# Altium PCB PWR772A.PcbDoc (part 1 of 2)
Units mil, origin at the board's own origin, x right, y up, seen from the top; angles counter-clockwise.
Board outline 3500 x 3300 mil, 4 copper layers (Top Layer, Signal Layer 1, Signal Layer 2, Bottom Layer), stack 30.2 mil thick; 164 components, 50 nets, 349 pads, 587 vias.
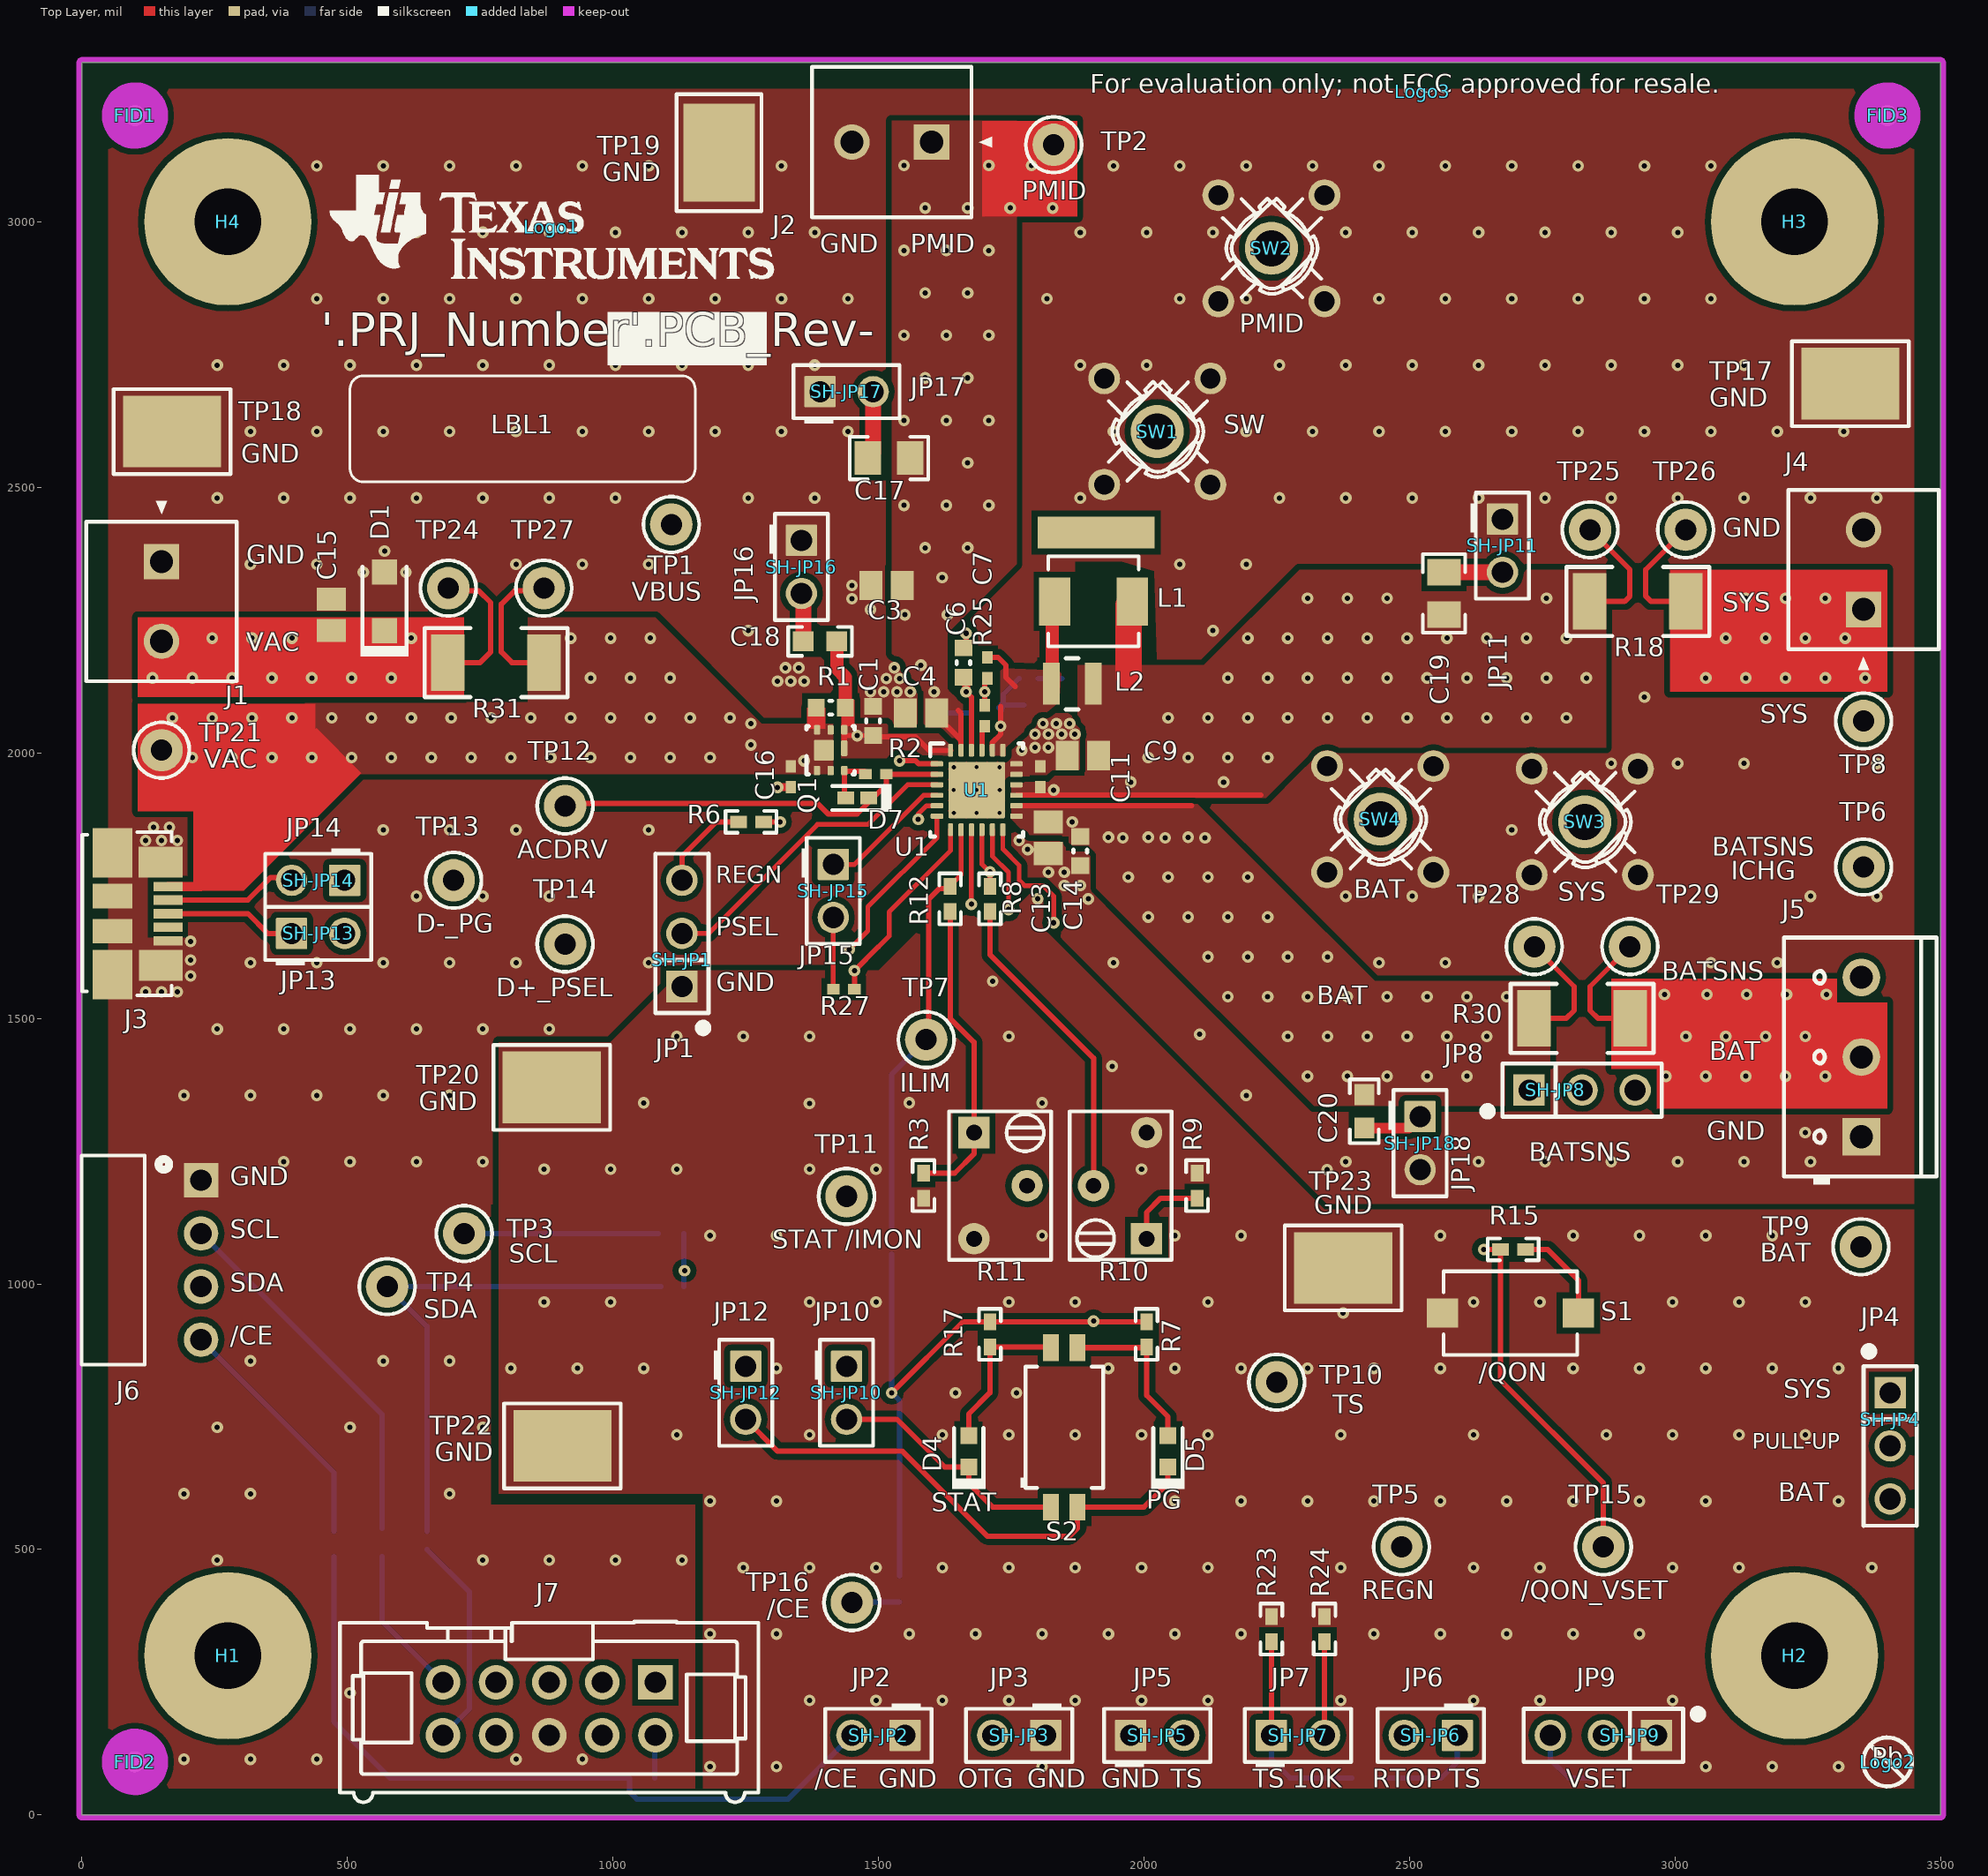
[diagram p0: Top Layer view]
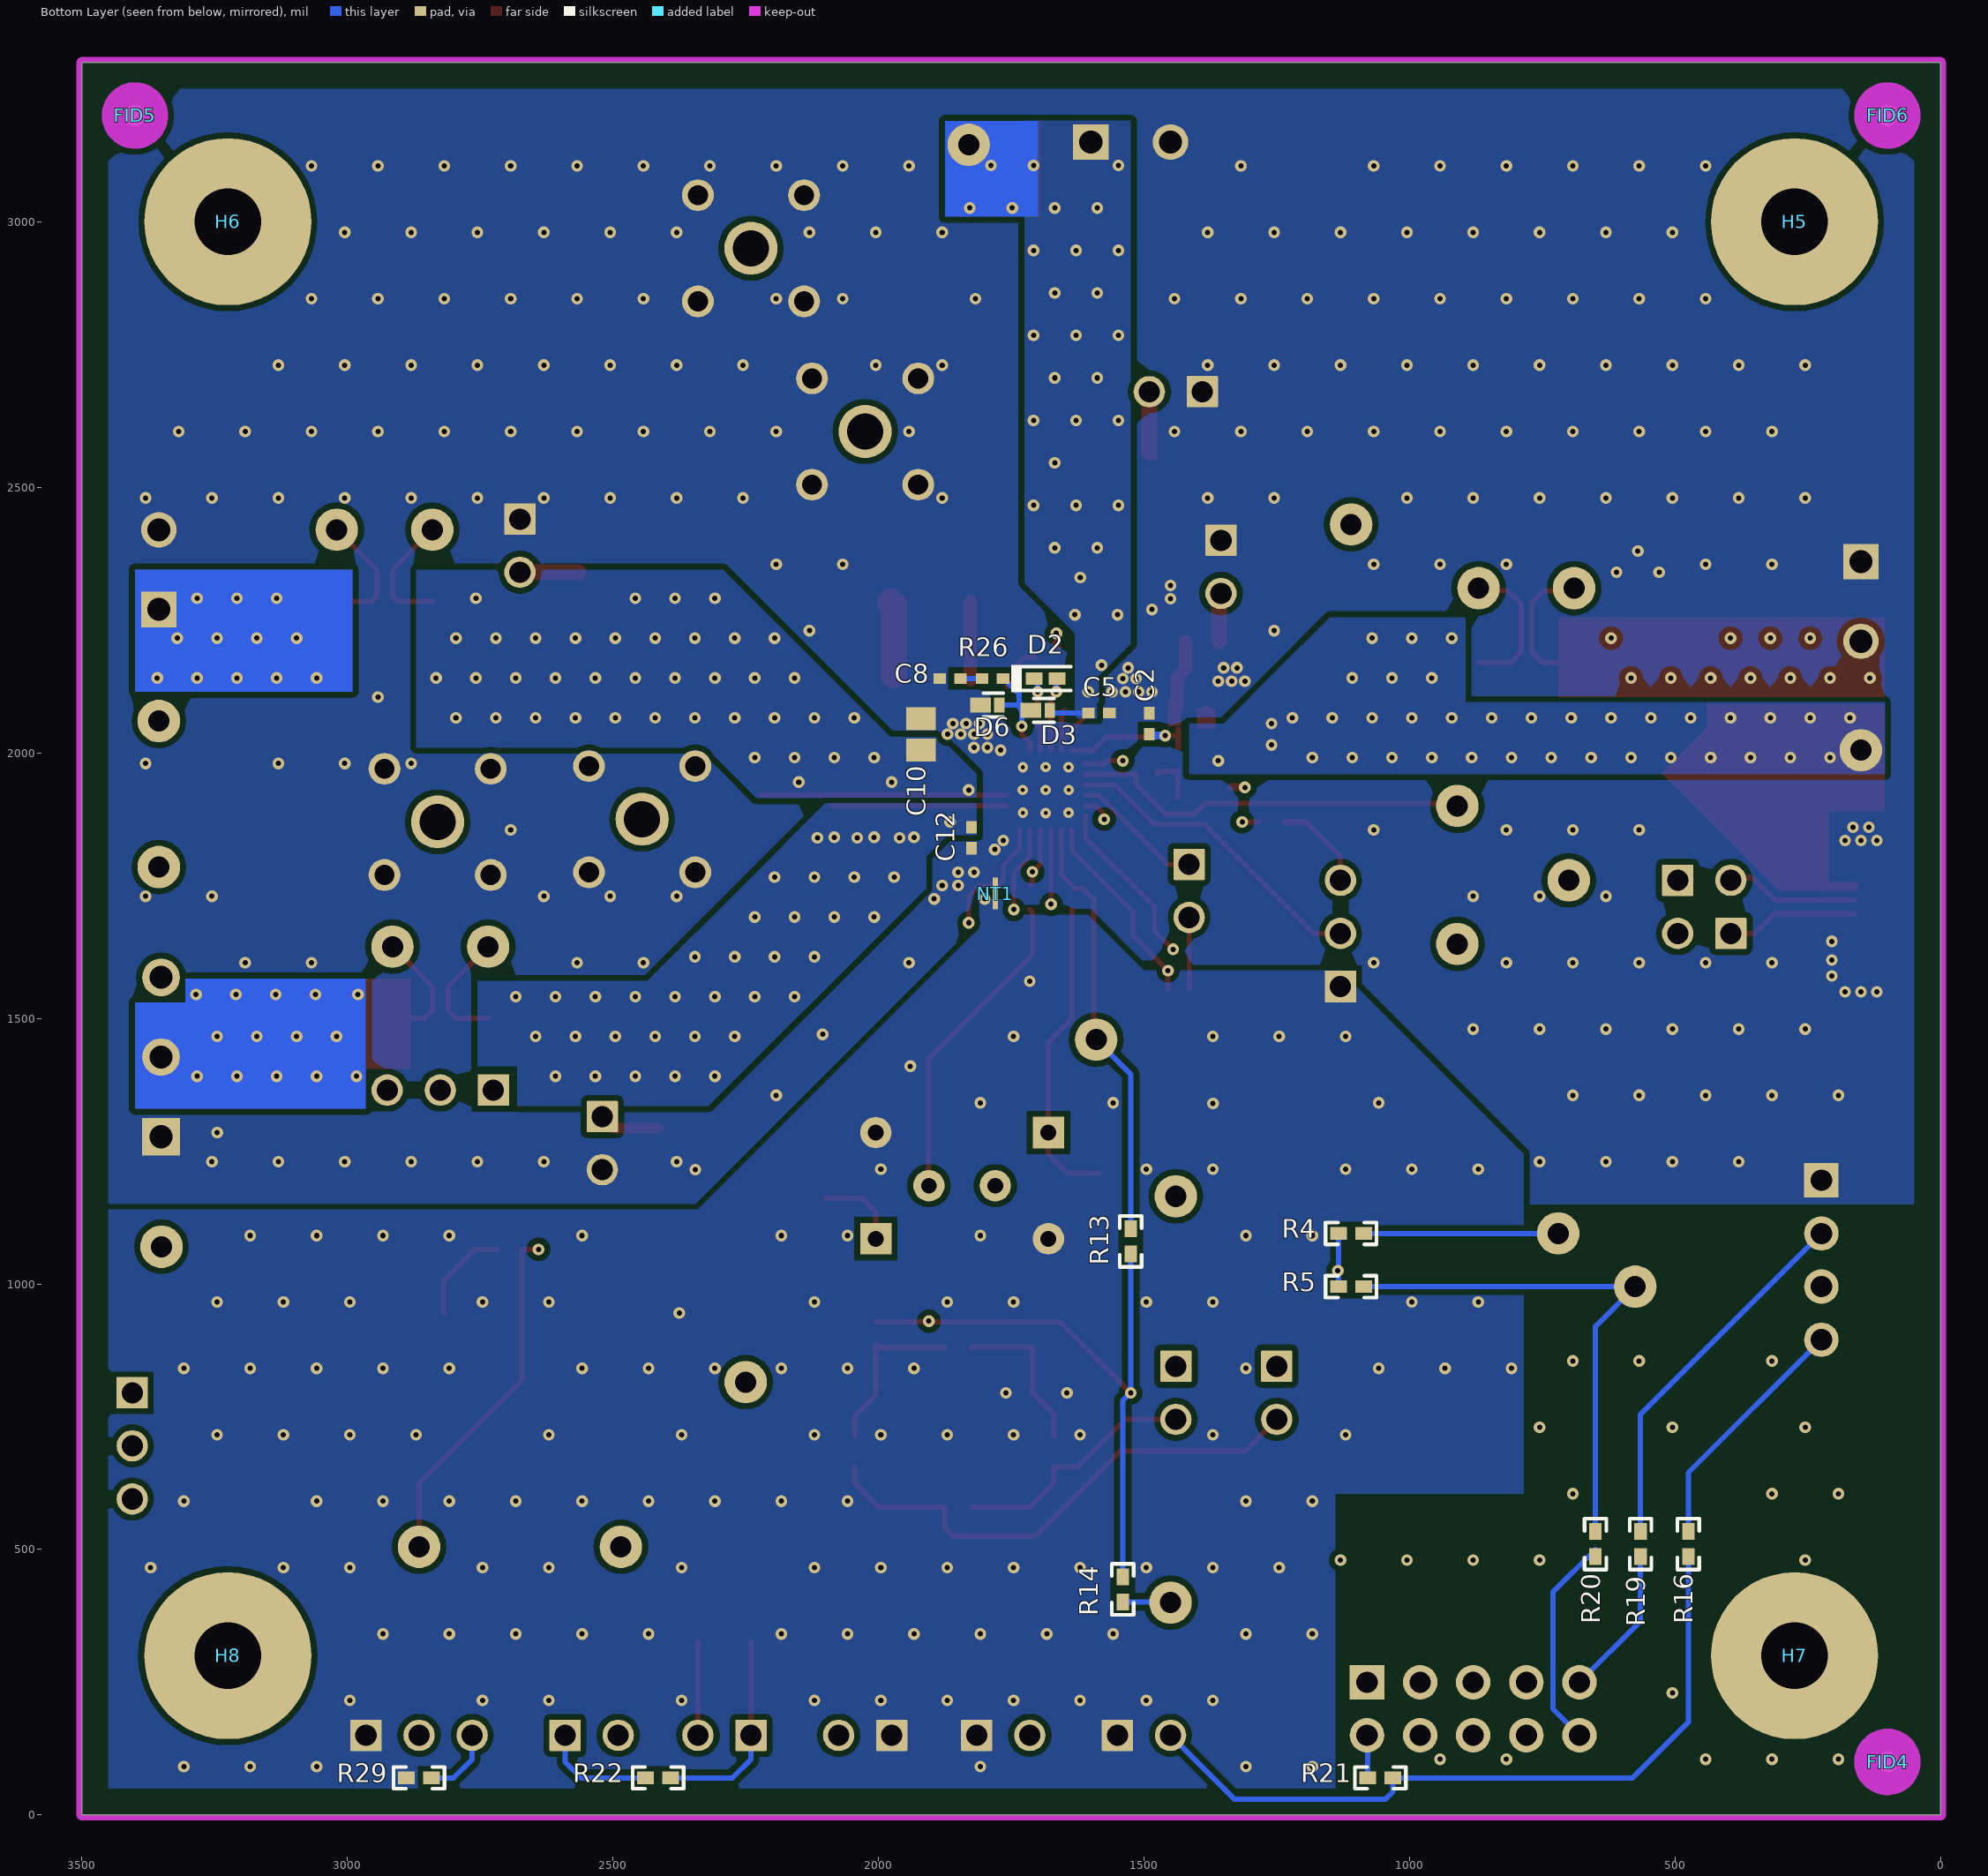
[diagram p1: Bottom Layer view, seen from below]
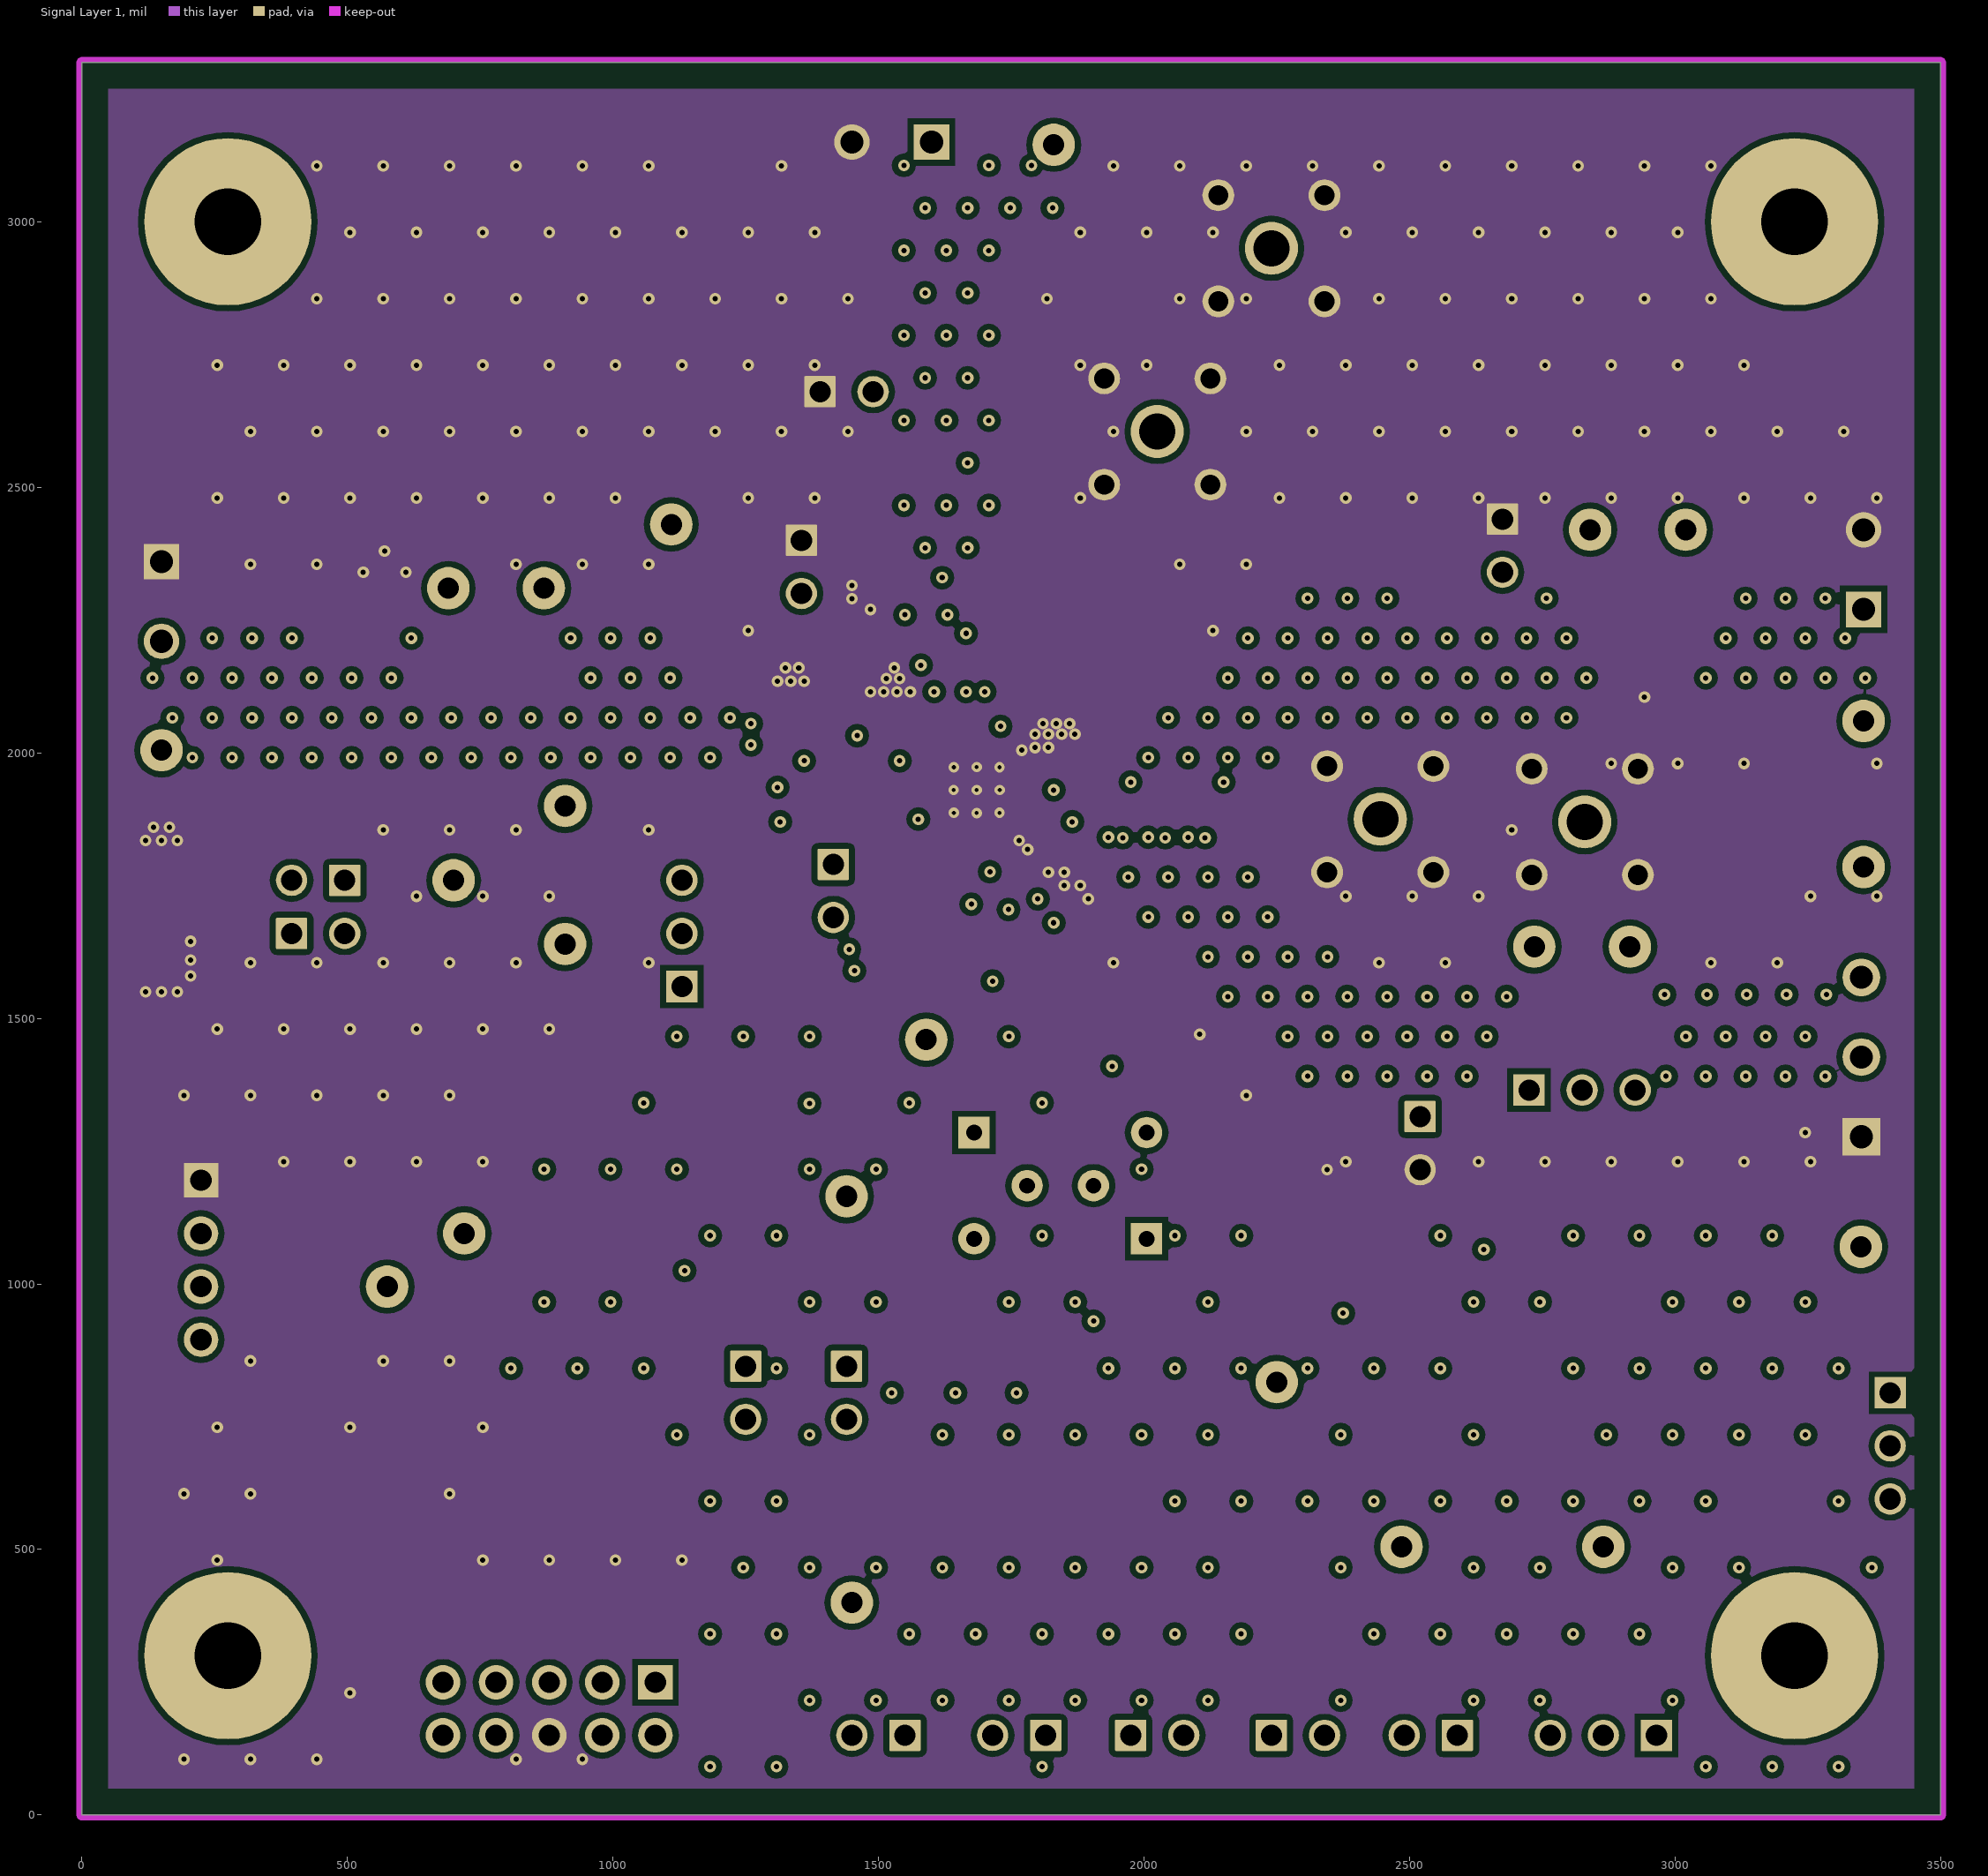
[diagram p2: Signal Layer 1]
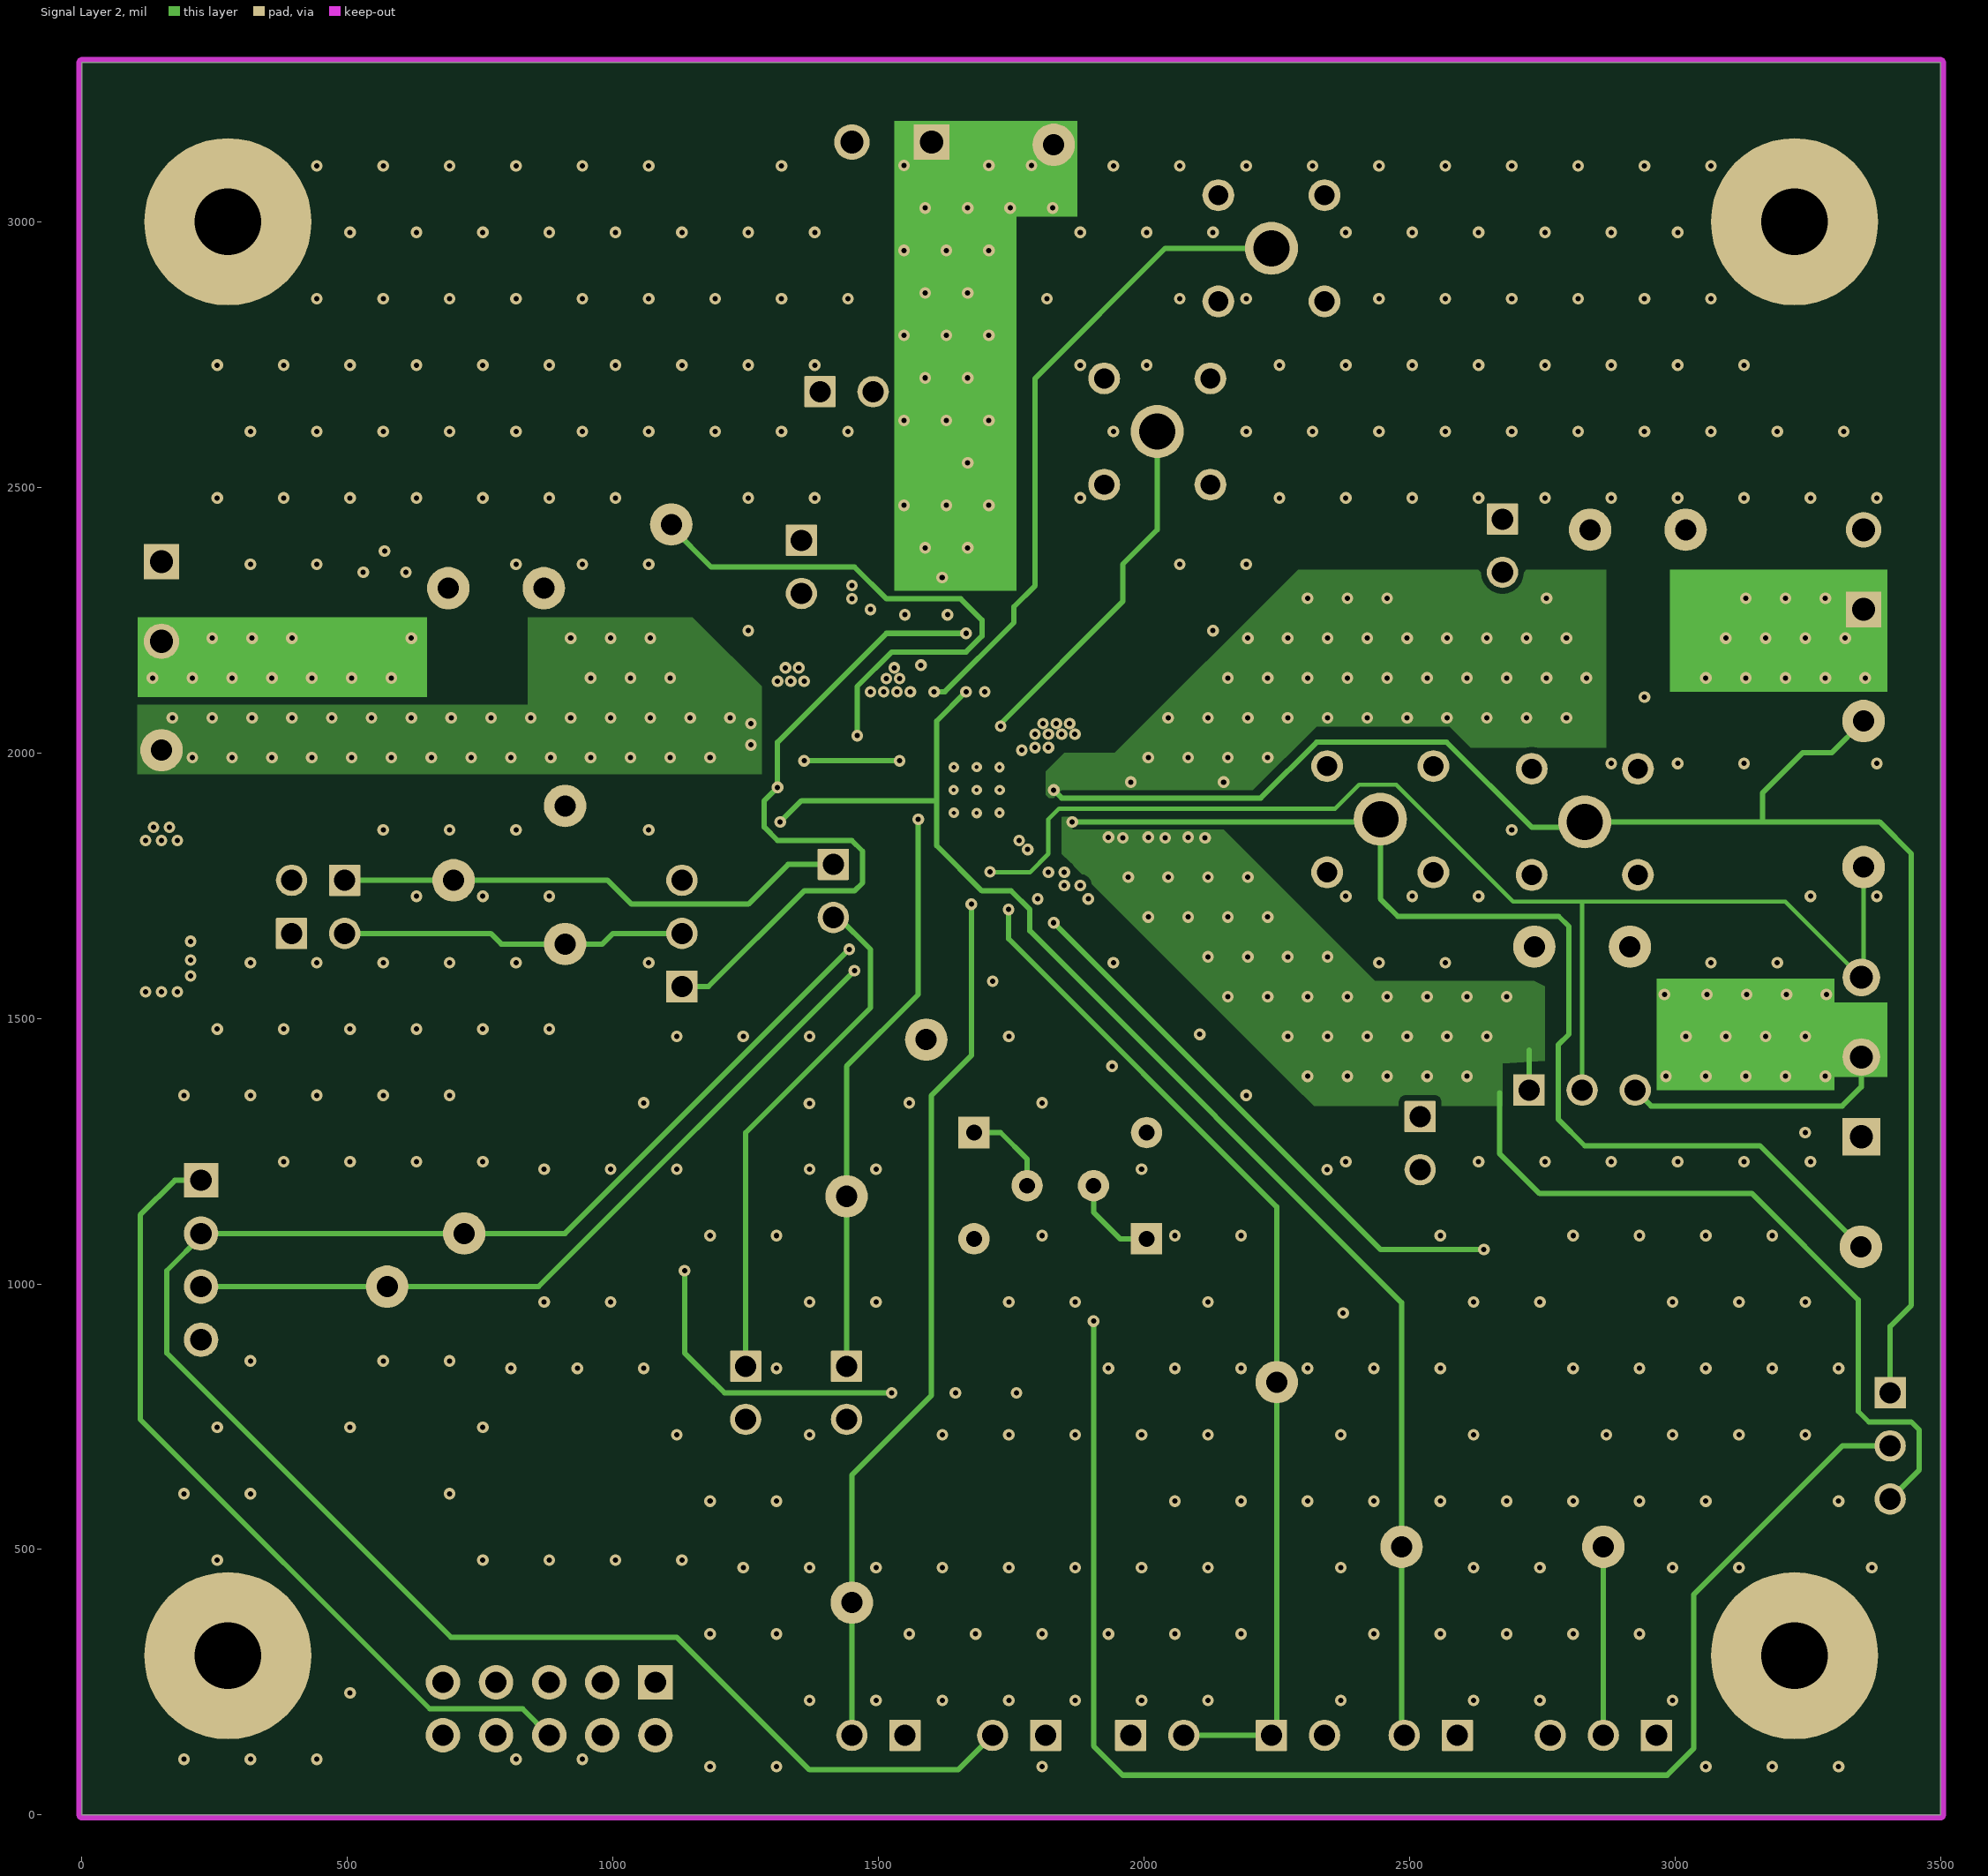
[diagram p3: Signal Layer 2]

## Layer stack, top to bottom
Top Solder: solder mask 0.4, Solder Resist, Dk 3.5
Top Layer: signal copper 1.4
Dielectric1: core 8.2, FR-4 High TG, Dk 4.8
Signal Layer 1: signal copper 1.4
Dielectric 2: core 8.2, FR-4 High TG, Dk 4.8
Signal Layer 2: signal copper 1.4
Dielectric 3: core 8.2, FR-4 High TG, Dk 4.8
Bottom Layer: signal copper 1.4
Bottom Solder: solder mask 0.4, Solder Resist, Dk 3.5

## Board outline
0,0 0,3300 3500,3300 3500,0

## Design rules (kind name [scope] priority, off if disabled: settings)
AcuteAngle [All] p1: minimum=4.50000000000000E+0001 checktracksonly=FALSE
AssemblyTestPointUsage [All] p1: valid=2
BoardOutlineClearance BoardOutlineClearance_MountingHoles [OnCopper and InComponentClass('Mounting Holes')] p1: gap=40
BoardOutlineClearance BoardOutlineClearance_Poly [OnCopper and InPoly] p2: gap=25
BoardOutlineClearance [OnCopper and Not InComponentClass('Logo') and not InComponentClass('FiducialMark') and not InRegion(1000,500,4000,800)] p3: gap=20
Clearance Clearance_D3-D6 [InComponent('D3')  or InComponent('D6')] p1: gap=7.8 except(5.1: SMDPad-SMDPad)
Clearance Clearance_Poly [InPolygon] p2: gap=11
Clearance [All] p3: gap=7.87
ComponentClearance ComponentClearance_JP13,14 [InComponent('JP13')  or InComponent('SH-JP13') vs InComponent('JP14')   or InComponent('SH-JP14')] p1: gap=0 collisioncheckmode=3 verticalgap=0 showdistances=FALSE
ComponentClearance ComponentClearance_MountingHoles_FiducialMarks [InComponentClass('Mounting Holes') vs InComponentClass('FiducialMark')] p2: gap=40 collisioncheckmode=3 verticalgap=10 showdistances=FALSE
ComponentClearance ComponentClearance_Shunt [InComponentClass('Header') vs InComponentClass('Shunt')] p3: gap=0 collisioncheckmode=3 verticalgap=0 showdistances=FALSE
ComponentClearance ComponentClearance_Logo [InComponentClass('Logo')] p4: gap=0 collisioncheckmode=3 verticalgap=0 showdistances=FALSE
ComponentClearance ComponentClearance_ScrewToNut [(HasFootprint('NY PMS 440 0025 PH')) vs (HasFootprint('Keystone_1902C'))] p5: gap=5 collisioncheckmode=3 verticalgap=10 showdistances=FALSE
ComponentClearance ComponentClearance_MountingHoles [InComponentClass('Mounting Holes')] p6: gap=40 collisioncheckmode=3 verticalgap=0 showdistances=FALSE
ComponentClearance ComponentClearance_SmallPassives [HasFootprint('0201*') or HasFootprint('0402*') or HasFootprint('0508') or HasFootprint('0603*') or HasFootprint('0612') or HasFootprint('0805*') or HasFootprint('0815*') or HasFootprint('0830*') or HasFootprint('1206*') or HasFootprint('1210*') or HasFootprint('1808*') or HasFootprint('1812*') or HasFootprint('1825*') or HasFootprint('2010*') or HasFootprint('2220*') or HasFootprint('2225*') or HasFootprint('2512*') or HasFootprint('2728*') or HasFootprint('3518*') vs HasFootprint('0201*') or HasFootprint('0402*') or HasFootprint('0508') or HasFootprint('0603*') or HasFootprint('0612') or HasFootprint('0805*') or HasFootprint('0815*') or HasFootprint('0830*') or HasFootprint('1206*') or HasFootprint('1210*') or HasFootprint('1808*') or HasFootprint('1812*') or HasFootprint('1825*') or HasFootprint('2010*') or HasFootprint('2220*') or HasFootprint('2225*') or HasFootprint('2512*') or HasFootprint('2728*') or HasFootprint('3518*')] p7: gap=10 collisioncheckmode=3 verticalgap=10 showdistances=FALSE
ComponentClearance ComponentClearance_THtoSMT [IsThruComponent vs IsSMTComponent] p8: gap=20 collisioncheckmode=3 verticalgap=20 showdistances=FALSE
ComponentClearance ComponentClearance_THtoTH [IsThruComponent vs IsThruComponent] p9: gap=30 collisioncheckmode=3 verticalgap=30 showdistances=FALSE
ComponentClearance [All] p10: gap=15 collisioncheckmode=3 verticalgap=10 showdistances=FALSE
DiffPairsRouting [All] p1: maxlimit=100 minlimit=10 mostfreqgap=10 toplayer_minwidth=15 toplayer_maxwidth=15 toplayer_prefwidth=15 midlayer1_minwidth=15 midlayer1_maxwidth=15 midlayer1_prefwidth=15 midlayer2_minwidth=15 midlayer2_maxwidth=15 midlayer2_prefwidth=15 bottomlayer_minwidth=15 bottomlayer_maxwidth=15 bottomlayer_prefwidth=15 maxuncoupledlength=1000
FabricationTestPointUsage TestPointUsage [All] p1: valid=2 allowmultiple=FALSE
FabricationTestpoint Testpoint [All] p1: side=3 testpointundercomponent=TRUE minsize=40 maxsize=100 preferedsize=60 minholesize=0 maxholesize=40 preferedholesize=32 testpointgrid=1 allowsidetop=TRUE allowsidebottom=TRUE usegrid=TRUE gridtolerance=0.01
FanoutControl Fanout_LCC [IsLCC] p1: bgadir=Out bgaviamode=Centered fanoutstyle=Auto fanoutdirection=Alternating viagrid=1 // Fanout_LCC (Default Rule)
FanoutControl Fanout_BGA [IsBGA] p2: bgadir=Out bgaviamode=Centered fanoutstyle=Auto fanoutdirection=Alternating viagrid=1 // Fanout_BGA (Default Rule)
FanoutControl Fanout_Default [All] p4: bgadir=Out bgaviamode=Centered fanoutstyle=Auto fanoutdirection=Alternating viagrid=1 // Fanout_Default (Default Rule)
FanoutControl Fanout_Small [(CompPinCount < 5)] p5: bgadir=Out bgaviamode=Centered fanoutstyle=Auto fanoutdirection=OutThenIn viagrid=1 // Fanout_Small (Default Rule)
HoleSize [All] p1: absolutevalues=TRUE maxlimit=251 minlimit=7.87 maxpercent=80.000 minpercent=20.000
HoleToHoleClearance HoleToHoleClearance_U1 [InComponent('U1') vs InComponent('U1')] p1: gap=0 allowstackedmicrovias=TRUE
HoleToHoleClearance [All] p2: gap=10 allowstackedmicrovias=TRUE
MinimumAnnularRing MinimumAnnularRing_ThermalPadVias [IsVia and InAnyComponent] p1: minimumring=5.91
MinimumAnnularRing [All] p2: minimumring=5.9
MinimumSolderMaskSliver MinimumSolderMaskSliver_Logo [InComponentClass('Logo') vs InComponentClass('Logo')] p1: minsoldermaskwidth=0.7
MinimumSolderMaskSliver [All] p2: minsoldermaskwidth=3.94
PlaneConnect [All] p1: planeconnectstyle=Relief reliefexpansion=10 reliefentries=4 reliefconductorwidth=10 reliefairgap=10
PolygonConnect [All] p1: connectstyle=Direct reliefconductorwidth=10 reliefentries=4 polygonreliefangle="90 Angle" airgapwidth=10
RoutingVias ThermalPadVias [IsVia and InAnyComponent] p1: holewidth=7.87 width=19.68 viastyle="Through Hole" minholewidth=7.87 minwidth=19.68 maxholewidth=12.99 maxwidth=23.62
RoutingVias [All] p2: holewidth=10 width=26 viastyle="Through Hole" minholewidth=7.87 minwidth=19 maxholewidth=40 maxwidth=65
SilkToBoardRegionClearance [Not ((IsComment or IsDesignator) And (Hide <> 'False')) and not InRegion(1000,500,4000,800)] p1:
SilkToSilkClearance SilkToSilkClearance_Pb-FreeLogo [(HasFootprint('Pb-Free_Overlay_Medium') OR HasFootprint('Pb-Free_Overlay_Small')) vs (HasFootprint('Pb-Free_Overlay_Medium') OR HasFootprint('Pb-Free_Overlay_Small'))] p1: silktosilkclearance=0
SilkToSilkClearance [All] p2: silktosilkclearance=3
SilkToSolderMaskClearance [Istrack and HasFootprint('152AD') vs isfill] p1: minsilkscreentomaskgap=1.7 clearancetoexposedcopper=FALSE
SilkToSolderMaskClearance SilkToComponentPadClearance [IsPad and InAnycomponent] p2: minsilkscreentomaskgap=3 clearancetoexposedcopper=TRUE
SilkToSolderMaskClearance "Silk to Solder Mask Opening" [All] p3: minsilkscreentomaskgap=3 clearancetoexposedcopper=FALSE
SolderMaskExpansion [All] p1: expansion=1.97
Width [All] p1: maxlimit=100 minlimit=7.8 preferedwidth=10 checkconnectedcopper=TRUE
14 further rules are at their usual default settings.

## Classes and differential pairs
component class PWR772A: C1 C2 C3 C4 C5 C6 C7 C8 C9 C10 C11 C12 C13 C14 C15 C16 C17 C18 C19 C20 D1 D2 D3 D4 D5 D6 D7 J1 J2 J3 J4 J5 J6 J7 JP1 JP2 JP3 JP4 JP5 JP6 JP7 JP8 JP9 JP10 JP11 JP12 JP13 JP14 JP15 JP16 JP17 JP18 L1 L2 NT1 Q1 R1 R2 R3 R4 R5 R6 R7 R8 R9 R10 R11 R12 R13 R14 R15 R16 R17 R18 R19 R20 R21 R22 R23 R24 R25 R26 R27 R29 R30 R31 S1 S2 SW1 SW2 SW3 SW4 TP1 TP2 TP3 TP4 TP5 TP6 TP7 TP8 TP9 TP10 TP11 TP12 TP13 TP14 TP15 TP16 TP17 TP18 TP19 TP20 TP21 TP22 TP23 TP24 TP25 TP26 TP27 TP28 TP29 U1
component class Header: JP1 JP2 JP3 JP4 JP5 JP6 JP7 JP8 JP9 JP10 JP11 JP12 JP13 JP14 JP15 JP16 JP17 JP18
component class Logo: Logo1
component class PWR772A_Hdwr: FID1 FID2 FID3 FID4 FID5 FID6 H1 H2 H3 H4 H5 H6 H7 H8 LBL1 Logo1 Logo2 Logo3 SH-JP1 SH-JP2 SH-JP3 SH-JP4 SH-JP5 SH-JP6 SH-JP7 SH-JP8 SH-JP9 SH-JP10 SH-JP11 SH-JP12 SH-JP13 SH-JP14 SH-JP15 SH-JP16 SH-JP17 SH-JP18 ZZ1 ZZ2 ZZ3 ZZ4 ZZ5
component class FiducialMark: FID1 FID2 FID3 FID4 FID5 FID6
component class AssemblyNote: ZZ1 ZZ2 ZZ3 ZZ4 ZZ5
component class Label: LBL1
component class "Mounting Holes": H1 H2 H3 H4
component class Shunt: SH-JP1 SH-JP2 SH-JP3 SH-JP4 SH-JP5 SH-JP6 SH-JP7 SH-JP8 SH-JP9 SH-JP10 SH-JP11 SH-JP12 SH-JP13 SH-JP14 SH-JP15 SH-JP16 SH-JP17 SH-JP18

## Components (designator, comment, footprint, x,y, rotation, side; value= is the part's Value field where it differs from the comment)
C1 "GMK107BJ105KA-T" 0603L 1490,2060 r90 top
C2 "GRM1555C1H102JA01D" 0402L 1490,2055 r90 bottom
C3 "GRM21BR61E106KA73L" 0805L 1515,2315 r180 top
C4 "GRM21BC71E106KE11L" 0805L 1580,2075 r180 top
C5 "GRM1555C1H102JA01D" 0402L 1585,2075 r180 bottom
C6 "GRM188R61C475KAAJ" 0603L 1660,2170 r90 top
C7 "GRM155R71E473KA88D" 0402L 1705,2160 r270 top
C8 "GRM1555C1E111JA01D" 0402L 1865,2140 r0 bottom
C9 "GRM21BR71A106KE51L" 0805L 1885,1995 r180 top
C10 "GRM21BR71A106KE51L" 0805L 1920,2035 r90 bottom
C11 "C1005X7R1E104M050BB" 0402L 1805,1955 r90 top
C12 "GRM1555C1H102JA01D" 0402L 1825,1840 r90 bottom
C13 "GRM21BR71A106KE51L" 0805L 1820,1840 r90 top
C14 "GRM188R61C475KAAJ" 0603L 1880,1815 r90 top
C15 "GRM219R71E105KA88D" 0805L 470,2260 r90 top
C16 "GRM155R71E104KE14D" 0402L 1335,1955 r270 top
C17 "GRM21BR61E106KA73L" 0805_HV 1520,2555 r180 top
C18 "GMK107BJ105KA-T" 0603 1390,2210 r180 top
C19 "GRM21BR71A106KE51L" 0805_HV 2565,2300 r90 top
C20 "GRM188R61C475KAAJ" 0603 2415,1325 r90 top
D1 "PTVS13VS1UR,115" SOD-123W 570,2285 r90 top
D2 "ZLLS350TA" SOD-523 1685,2140 r180 bottom
D3 "NSR10F20NXT5G" 152AD 1700,2080 r0 bottom
D4 "LTST-C190GKT" LED_LTST-C190 1670,685 r270 top
D5 "LTST-C190GKT" LED_LTST-C190 2045,685 r270 top
D6 "NSR10F20NXT5G" 152AD 1795,2090 r0 bottom
D7 "ZLLS350TA" SOD-523 1460,1915 r180 top
FID1 "Fiducial" Fiducial10-30 100,3200 r0 top
FID2 "Fiducial" Fiducial10-30 100,100 r0 top
FID3 "Fiducial" Fiducial10-30 3400,3200 r0 top
FID4 "Fiducial" Fiducial10-30 100,100 r90 bottom
FID5 "Fiducial" Fiducial10-30 3400,3200 r90 bottom
FID6 "Fiducial" Fiducial10-30 100,3200 r90 bottom
H1 "NY PMS 440 0025 PH" "NY PMS 440 0025 PH" 275,300 r0 top
H2 "NY PMS 440 0025 PH" "NY PMS 440 0025 PH" 3225,300 r0 top
H3 "NY PMS 440 0025 PH" "NY PMS 440 0025 PH" 3225,3000 r0 top
H4 "NY PMS 440 0025 PH" "NY PMS 440 0025 PH" 275,3000 r0 top
H5 "1902C" Keystone_1902C 275,3000 r180 bottom
H6 "1902C" Keystone_1902C 3225,3000 r180 bottom
H7 "1902C" Keystone_1902C 275,300 r180 bottom
H8 "1902C" Keystone_1902C 3225,300 r180 bottom
J1 "1727010" PhoenixConact_1727010 150,2285 r270 top
J2 "1727010" PhoenixConact_1727010 1525,3150 r180 top
J3 "0473460001" CONN_47346-0001 0.75,1697.13 r90 top
J4 "1727010" PhoenixConact_1727010 3355,2345 r90 top
J5 "1727023" Phoenix_1727023 3350.75,1427.13 r90 top
J6 "22-05-3041" CONN_22-05-3041 0,1045 r270 top
J7 "N2510-6002-RB" CONN_2510-6002 880,200 r180 top
JP1 "PEC03SAAN" CONN_PEC03SAAN 1130,1660 r90 top
JP2 "PEC02SAAN" CONN_PEC02SAAN 1500,150 r180 top
JP3 "PEC02SAAN" CONN_PEC02SAAN 1765,150 r180 top
JP4 "PEC03SAAN" CONN_PEC03SAAN 3405,695 r270 top
JP5 "PEC02SAAN" CONN_PEC02SAAN 2025,150 r0 top
JP6 "PEC02SAAN" CONN_PEC02SAAN 2540,150 r180 top
JP7 "PEC02SAAN" CONN_PEC02SAAN 2290,150 r0 top
JP8 "PEC03SAAN" CONN_PEC03SAAN 2825,1365 r0 top
JP9 "PEC03SAAN" CONN_PEC03SAAN 2865,150 r180 top
JP10 "PEC02SAAN" CONN_PEC02SAAN 1440,795 r270 top
JP11 "PEC02SAAN" CONN_PEC02SAAN 2675,2390 r270 top
JP12 "PEC02SAAN" CONN_PEC02SAAN 1250,795 r270 top
JP13 "PEC02SAAN" CONN_PEC02SAAN 445,1660 r0 top
JP14 "PEC02SAAN" CONN_PEC02SAAN 445,1760 r180 top
JP15 "PEC02SAAN" CONN_PEC02SAAN 1415,1740 r270 top
JP16 "PEC02SAAN" CONN_PEC02SAAN 1355,2350 r270 top
JP17 "PEC02SAAN" CONN_PEC02SAAN 1440,2680 r0 top
JP18 "PEC02SAAN" CONN_PEC02SAAN 2520,1265 r270 top
L1 "74437321010" WE-LHMI_4012 1905,2285 r0 top
L2 "MPIM252010F1R0M-LF" MPIM252010F 1865,2130 r0 top
LBL1 "Size: 0.65\" x 0.20 \"" Label_650x200 830,2610 r0 top
Logo1 "Texas Instruments" TI_Stacked_Overlay_Small 885,2990 r0 top
Logo2 "Pb-Free Symbol" Pb-Free_Overlay_Small 3400,100 r0 top
Logo3 "FCC disclaimer" FCC_disclaimer 2525,3245 r0 top
NT1 "Net-Tie" Net-Tie_10milWide_30milLong 1780,1735 r270 bottom net-tie
Q1 "CSD17571Q2" DQK0006C 1410,2005 r90 top
R1 "CRCW06030000Z0EA" 0603L 1410,2085 r0 top
R2 "CRCW04020000Z0ED" 0402L 1495,1960 r180 top
R3 "CRCW04021K00FKED" 0402 1585,1185 r90 top
R4 "CRCW04022K21FKED" 0402 1110,1095 r180 bottom
R5 "CRCW040210K0FKED" 0402 1110,995 r180 bottom
R6 "CRCW040210K0FKED" 0402 1260,1870 r0 top
R7 "CRCW04022K21FKED" 0402 2005,905 r90 top
R8 "CRCW0402221RFKED" 0402 1710,1725 r90 top
R9 "CRCW04022K80FKED" 0402 2100,1185 r270 top
R10 "3266W-1-103LF" TRIM_3266W 2005,1085 r180 top
R11 "3266W-1-103LF" TRIM_3266W 1680,1285 r0 top
R12 "CRCW0402158RFKED" 0402 1635,1725 r90 top
R13 "CRCW040210K0FKED" 0402 1525,1080 r90 bottom
R14 "CRCW040210K0FKED" 0402 1540,425 r270 bottom
R15 "CRCW04024K70JNED" 0402 2695,1065 r180 top
R16 "CRCW04020000Z0ED" 0402 475,510 r270 bottom
R17 "CRCW04022K21FKED" 0402 1710,905 r90 top
R18 "WSL2010R0100FEA18" 2010 2930,2285 r0 top
R19 "CRCW0402200RFKED" 0402 565,510 r270 bottom
R20 "CRCW0402200RFKED" 0402 650,510 r90 bottom
R21 "CRCW04020000Z0ED" 0402 1055,70 r180 bottom
R22 "CRCW04025K23FKED" 0402 2415,70 r0 bottom
R23 "CRCW040230K1FKED" 0402 2240,350 r270 top
R24 "CRCW040210K0FKED" 0402 2340,350 r270 top
R25 "CRCW04020000Z0ED" 0402L 1700,2070 r270 top
R26 "CRCW040210R0JNED" 0402L 1785,2140 r180 bottom
R27 "CRCW04020000Z0ED" 0402L 1435,1555 r180 top
R29 "CRCW040210K0FKED" 0402 2865,70 r180 bottom
R30 "WSL2010R0100FEA18" 2010 2825,1500 r0 top
R31 "WSL2010R0100FEA18" 2010 780,2170 r0 top
S1 "KSR221GLFS" KSR 2690,945 r180 top
S2 "218-2LPST" SW_218-2LP 1850,730 r90 top
SH-JP1 "969102-0000-DA" SNT-100-BK-G 1130,1610 r90 top
SH-JP2 "969102-0000-DA" SNT-100-BK-G 1500,150 r180 top
SH-JP3 "969102-0000-DA" SNT-100-BK-G 1765,150 r180 top
SH-JP4 "969102-0000-DA" SNT-100-BK-G 3405,745 r90 top
SH-JP5 "969102-0000-DA" SNT-100-BK-G 2025,150 r0 top
SH-JP6 "969102-0000-DA" SNT-100-BK-G 2540,150 r180 top
SH-JP7 "969102-0000-DA" SNT-100-BK-G 2290,150 r0 top
SH-JP8 "969102-0000-DA" SNT-100-BK-G 2775,1365 r180 top
SH-JP9 "969102-0000-DA" SNT-100-BK-G 2915,150 r0 top
SH-JP10 "969102-0000-DA" SNT-100-BK-G 1440,795 r90 top
SH-JP11 "969102-0000-DA" SNT-100-BK-G 2675,2390 r90 top
SH-JP12 "969102-0000-DA" SNT-100-BK-G 1250,795 r90 top
SH-JP13 "969102-0000-DA" SNT-100-BK-G 445,1660 r180 top
SH-JP14 "969102-0000-DA" SNT-100-BK-G 445,1760 r0 top
SH-JP15 "969102-0000-DA" SNT-100-BK-G 1415,1740 r90 top
SH-JP16 "969102-0000-DA" SNT-100-BK-G 1355,2350 r90 top
SH-JP17 "969102-0000-DA" SNT-100-BK-G 1440,2680 r0 top
SH-JP18 "969102-0000-DA" SNT-100-BK-G 2520,1265 r90 top
SW1 "SW" Tek_131-5031-00 2025,2605 r0 top
SW2 "PMID" Tek_131-5031-00 2240,2950 r0 top
SW3 "SYS" Tek_131-5031-00 2830,1870 r0 top
SW4 "BAT" Tek_131-5031-00 2445,1875 r0 top
TP1 "5000" Keystone5000 1110,2430 r0 top
TP2 "5000" Keystone5000 1830,3145 r0 top
TP3 "5002" Keystone5002 720,1095 r0 top
TP4 "5002" Keystone5002 575,995 r0 top
TP5 "5003" Keystone5003 2485,505 r0 top
TP6 "5002" Keystone5002 3355,1785 r0 top
TP7 "5002" Keystone5002 1590,1460 r180 top
TP8 "5003" Keystone5003 3355,2060 r0 top
TP9 "5004" Keystone5004 3350,1070 r0 top
TP10 "5002" Keystone5002 2250,815 r270 top
TP11 "5002" Keystone5002 1440,1165 r180 top
TP12 "5002" Keystone5002 910,1900 r0 top
TP13 "5002" Keystone5002 700,1760 r90 top
TP14 "5002" Keystone5002 910,1640 r90 top
TP15 "5002" Keystone5002 2865,505 r0 top
TP16 "5002" Keystone5002 1450,400 r0 top
TP17 "5016" Testpoint_Keystone_Compact 3330,2695 r0 top
TP18 "5016" Testpoint_Keystone_Compact 170,2605 r0 top
TP19 "5016" Testpoint_Keystone_Compact 1200,3130 r90 top
TP20 "5016" Testpoint_Keystone_Compact 885,1370 r0 top
TP21 "5002" Keystone5002 150,2005 r0 top
TP22 "5016" Testpoint_Keystone_Compact 905,695 r0 top
TP23 "5016" Testpoint_Keystone_Compact 2375,1030 r0 top
TP24 "5002" Keystone5002 690,2310 r270 top
TP25 "5002" Keystone5002 2840,2420 r270 top
TP26 "5002" Keystone5002 3020,2420 r270 top
TP27 "5002" Keystone5002 870,2310 r270 top
TP28 "5002" Keystone5002 2735,1635 r270 top
TP29 "5002" Keystone5002 2915,1635 r270 top
U1 "=PartNumber" RGE0024H 1685,1930 r0 top
U1 "BQ25600RTWR" RTW0024H 1685,1930 r0 top
ZZ1 "This Assembly Note is for PCB labels only" AssemblyNoteLabel 170,3920 r0 top
ZZ2 "These assemblies are ESD sensitive, ESD precautions shall be observed." AssemblyNote 170,3830 r0 top
ZZ3 "These assemblies must be clean and free from flux and all contaminants. Use of no clean flux is not acceptable." AssemblyNote 170,3740 r0 top
ZZ4 "These assemblies must comply with workmanship standards IPC-A-610 Class 2, unless otherwise specified." AssemblyNote 170,3650 r0 top
ZZ5 "Switch S2 toggles shall be in 'OFF' positions after assembly" AssemblyNote 170,3560 r0 top

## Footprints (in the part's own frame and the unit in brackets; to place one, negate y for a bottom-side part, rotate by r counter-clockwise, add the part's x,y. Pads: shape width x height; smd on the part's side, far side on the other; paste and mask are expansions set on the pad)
152AD [mm] "ON SEMICONDUCTOR, DSN2, 1.4x0.6, 0.75P"
  rect 0.5x0.7 smd paste-0.05 mask-2: 1(-0.575,0)
  rect 1x0.7 smd paste-0.05 mask-2: 2(0.325,0)
  silkscreen extent -0.77,-0.58 0.2,0.58, body extent -0.73,-0.3 0.66,0.3, height 0.32
0402 [mm] "0402 from SM-752 data"
  rect 0.8x0.6 smd: 1(-0.6,0) 2(0.6,0)
  silkscreen extent -1.22,-0.52 1.22,0.52, body extent -0.55,-0.3 0.55,0.3, height 0.6
0402L [mm] "0402 from SM-752 data"
  rect 0.6x0.5 smd: 1(-0.5,0) 2(0.5,0)
  body extent -0.55,-0.3 0.55,0.3, height 0.6
0603 [mm] "0603 from SM-752 data"
  rect 1x0.95 smd: 1(-0.8,0) 2(0.8,0)
  silkscreen extent -1.52,-0.69 1.52,0.69, body extent -0.87,-0.47 0.87,0.47, height 1
0603L [mm] "0603 from SM-752 data"
  rect 0.8x0.85 smd: 1(-0.7,0) 2(0.7,0)
  silkscreen extent -0.07,-0.33 0.07,0.33, body extent -0.87,-0.47 0.87,0.47, height 1
0805_HV [mil] "0805 with 30mil clearance between pads"
  rect 50x63 smd: 1(-40,0) 2(40,0)
  silkscreen extent -74,-40 74,40, body extent -43,-29 43,29, height 57
0805L [mm] "0805 from SM-752 data"
  rect 1.1x1.4 smd: 1(-0.75,0) 2(0.75,0)
  body extent -1.1,-0.72 1.1,0.72, height 1.45
2010 [mm] "Chip Capacitor, Body 5.08x2.54mm, IPC Medium Density"
  rect 1.6x2.7 smd: 1(-2.3,0) 2(2.3,0)
  silkscreen extent -3.42,-1.65 3.42,1.65, body extent -2.73,-1.45 2.73,1.45, height 1.66
AssemblyNote [mil] "Assembly Note"
AssemblyNoteLabel [mil] "Assembly Note for PCB Labels"
CONN_22-05-3041 [mm] "MOLEX"
  rect 1.65x1.65 hole 1.02: 1(-3.81,5.7)
  round 1.65 hole 1.02: 2(-1.27,5.7) 3(1.27,5.7) 4(3.81,5.7)
  silkscreen extent -5,0 5,4.18, body extent -5,-6.91 5,6.02, height 6.37
CONN_2510-6002 [mm] "3M 2500 series TS-0770-L December 15, 2011"
  rect 1.65x1.65 hole 1.016 mask+0: 1(-5.08,-1.27)
  round 1.65 hole 1.016 mask+0: 2(-5.08,1.27) 3(-2.54,-1.27) 4(-2.54,1.27) 5(0,-1.27) 6(0,1.27) 7(2.54,-1.27) 8(2.54,1.27) 9(5.08,-1.27) 10(5.08,1.27)
  silkscreen extent -10.01,-4.17 10.01,4.47, body extent -10.01,-4.11 10.01,4.52, height 9.92
CONN_47346-0001 [mm] "MOLEX"
  rect 0.45x1.38 smd: 1(1.3,-4.105) 2(0.65,-4.105) 3(0,-4.105) 4(-0.65,-4.105) 5(-1.3,-4.105)
  rect 1.475x2.1 smd: 6(-2.462,-3.755) 11(2.463,-3.75)
  rect 2.375x1.9 smd: 7(-2.912,-1.45) 10(2.912,-1.45)
  rect 1.175x1.9 smd: 8(-0.837,-1.45) 9(0.837,-1.45)
  silkscreen extent -3.9,-4.28 3.9,0, body extent -3.99,-4.43 3.99,1, height 2.72
CONN_PEC02SAAN [mm] "SULLINS"
  rrect7% 1.5x1.5 hole 1.016: 1(-1.27,0)
  round 1.5 hole 1.016: 2(1.27,0)
  silkscreen extent -2.54,-1.52 2.54,1.27, body extent -2.54,-1.27 2.54,1.27, height 8.38
CONN_PEC03SAAN [mm] "SULLINS"
  rect 1.5x1.5 hole 1.016: 1(-2.54,0)
  round 1.5 hole 1.016: 2(0,0) 3(2.54,0)
  silkscreen extent -4.72,-1.27 3.81,1.27, body extent -3.84,-1.3 3.84,1.3, height 8.38
DQK0006C [mm] "WSON"
  rrect12% 0.9x0.86 on Top Paste: 0(0,0.325)
  rrect34% 0.7x0.29 on Top Paste: 0(0.095,-0.65)
  rrect33% 0.45x0.3 smd: 1(-0.975,0.65) 2(-0.975,0) 3(-0.975,-0.65) 4(0.975,-0.65) 5(0.975,0) 6(0.975,0.65)
  rrect33% 0.75x0.3 smd paste-0.15: 7(0.095,-0.65)
  rrect11% 1x0.95 smd paste-0.5: 8(0,0.325)
  silkscreen extent -1.15,-1.15 1.15,1.15, body extent -1,-1 1,1, height 0.82
FCC_disclaimer [mil]
Fiducial10-30 [mm]
  round 1 smd mask+1: 1(0,0)
  Top Layer keep-out circle w1.678: c0,0 r0.75
Keystone5000 [mil] "For Keystone 500x miniature loop terminals"
  round 80 hole 40: 1(0,0)
  silkscreen extent -52,-52 52,52, body extent -49,-49 49,49, height 182
Keystone5002 [mil] "For Keystone 500x miniature loop terminals"
  round 80 hole 40: 1(0,0)
  silkscreen extent -52,-52 52,52, body extent -49,-49 49,49, height 182
Keystone5003 [mil] "For Keystone 500x miniature loop terminals"
  round 80 hole 40: 1(0,0)
  silkscreen extent -52,-52 52,52, body extent -49,-49 49,49, height 182
Keystone5004 [mil] "For Keystone 500x miniature loop terminals"
  round 80 hole 40: 1(0,0)
  silkscreen extent -52,-52 52,52, body extent -49,-49 49,49, height 182
Keystone_1902C [mil] "Hex Standoff, 4-40 threaded, nylon"
  round 1 on Mech4: 0(0,0)
  body extent -145,-126 146,126, height 501
KSR [mm] "C&K Components SPST switch"
  rect 1.5x1.4 smd: 1(-3.25,0) 2(3.25,0)
  silkscreen extent -3.2,-2 3.2,2, body extent -3,-1.9 3,1.9, height 2.65
Label_650x200 [mil] "Thermal Transfer Label"
  round 1 on Mech13: 0(0,0)
  silkscreen extent -325,-100 325,100, body extent -325,-100 325,100, height 1
LED_LTST-C190 [mm] "Lite-On"
  rect 0.8x0.8 smd: 1(-0.75,0) 2(0.75,0)
  silkscreen extent -1.1,-0.8 1.8,0.8, body extent -0.85,-0.45 0.85,0.45, height 0.9
MPIM252010F [mm] "SMD, 2-Leads, Body 2.5x2mm"
  rect 0.8x2 smd: 1(-1,0) 2(1,0)
  silkscreen extent -0.3,-1.22 0.3,1.22, body extent -1.38,-1.12 1.38,1.12, height 1
Net-Tie_10milWide_30milLong [mil] "10mil net tie, no solder mask opening, no solder paste"
  rect 30x10 smd paste-5 mask-5: 1(-15,0) 2(15,0)
"NY PMS 440 0025 PH" [mm] "4-40 nylon screw and mounting hole"
  round 8 hole 3.2: 1(0,0)
  body extent -3.3,-3.3 3.3,3.3, height 2.69
Pb-Free_Overlay_Small [mil]
  silkscreen extent -46,-46 46,46
Phoenix_1727023 [mm] "Phoenix Contact"
  rect 1.8x1.8 hole 1.1: 1(-3.81,0)
  round 1.8 hole 1.1: 2(0,0) 3(3.81,0)
  silkscreen extent -6.1,-3.6 5.72,3.7, body extent -5.71,-3.6 5.72,3.7, height 8.5
PhoenixConact_1727010 [mm]
  rect 1.7x1.7 hole 1.1: 1(-1.905,0)
  round 1.7 hole 1.1: 2(1.905,0)
  silkscreen extent -4.8,-3.6 3.81,3.6, body extent -3.81,-3.6 3.81,3.7, height 8.52
RGE0024H [mm] "QFN, 24-Leads, Body 4x4mm, Pitch 0.5mm, Thermal Pad 2.7x2.7mm, TI Recommended"
  rrect40% 0.6x0.25 smd: 1(-1.9,1.25) 2(-1.9,0.75) 3(-1.9,0.25) 4(-1.9,-0.25) 5(-1.9,-0.75) 6(-1.9,-1.25) 13(1.9,-1.25) 14(1.9,-0.75) 15(1.9,-0.25) 16(1.9,0.25) 17(1.9,0.75) 18(1.9,1.25)
  rrect40% 0.25x0.6 smd: 7(-1.25,-1.9) 8(-0.75,-1.9) 9(-0.25,-1.9) 10(0.25,-1.9) 11(0.75,-1.9) 12(1.25,-1.9) 19(1.25,1.9) 20(0.75,1.9) 21(0.25,1.9) 22(-0.25,1.9) 23(-0.75,1.9) 24(-1.25,1.9)
  rrect4% 2.7x2.7 smd paste-1.35: 25(0,0)
  silkscreen extent -2.22,-2.22 2.22,2.22, body extent -2.07,-2.07 2.07,2.07, height 1.01
RTW0024H [mm] "QFN, 24-Leads, Body 4x4mm, Pitch 0.5mm, Thermal Pad 2.7x2.7mm"
  rrect42% 0.6x0.24 smd: 1(-1.9,1.25) 2(-1.9,0.75) 3(-1.9,0.25) 4(-1.9,-0.25) 5(-1.9,-0.75) 6(-1.9,-1.25) 13(1.9,-1.25) 14(1.9,-0.75) 15(1.9,-0.25) 16(1.9,0.25) 17(1.9,0.75) 18(1.9,1.25)
  rrect42% 0.24x0.6 smd: 7(-1.25,-1.9) 8(-0.75,-1.9) 9(-0.25,-1.9) 10(0.25,-1.9) 11(0.75,-1.9) 12(1.25,-1.9) 19(1.25,1.9) 20(0.75,1.9) 21(0.25,1.9) 22(-0.25,1.9) 23(-0.75,1.9) 24(-1.25,1.9)
  rrect8% 1.19x1.19 on Top Paste: 25(-0.695,-0.695) 25(-0.695,0.695) 25(0.695,-0.695) 25(0.695,0.695)
  rrect4% 2.7x2.7 smd paste-1.35: 25(0,0)
  silkscreen extent -2.22,-2.22 2.22,2.22, body extent -2,-2 2,2, height 0.8
SNT-100-BK-G [mil] "Samtec STEP model"
  round 1 on Mech3: 0(0,0)
  body extent -100,-50 100,50, height 344
SOD-123W [mm] "NXP recommended land pattern"
  rect 1.2x1.2 smd paste-0.05: 1(-1.4,0) 2(1.4,0)
  silkscreen extent -2.64,-1.14 1.68,1.14, body extent -1.85,-0.95 1.85,0.95, height 1.1
SOD-523 [mm] "NXP Semiconductor recommended land pattern, nominal STEP model"
  rect 0.8x0.6 smd paste-0.05: 1(-0.55,0) 2(0.55,0)
  silkscreen extent -1.65,-0.66 1.2,0.66, body extent -0.8,-0.4 0.8,0.4, height 0.72
SW_218-2LP [mm] "SMD, 4-Leads, Body 3.71x5.8mm, Pitch 1.27mm"
  rect 1.27x0.76 smd: 1(-3.81,0.635) 2(-3.81,-0.635) 3(3.81,-0.635) 4(3.81,0.635)
  silkscreen extent -2.9,-1.86 2.9,2.09, body extent -4.22,-1.86 4.22,1.85, height 2.62
Tek_131-5031-00 [mil] "Tektronix cold nose probe"
  round 100 hole 68: 1(0,0)
  round 60 hole 38: 2(-100,100) 3(-100,-100) 4(100,-100) 5(100,100)
  silkscreen extent -92,-93 94,94, body extent -206,-206 206,206, height 351
Testpoint_Keystone_Compact [mil] "Compact SMT test point"
  rect 185x135 smd: 1(0,0)
  silkscreen extent -110,-80 110,80, body extent -75,-56 75,56, height 91
TI_Stacked_Overlay_Small [mil]
  silkscreen extent -418,-98 418,98
TRIM_3266W [mm] "Bourns 3266W series REV 08/10"
  rect 1.5x1.5 hole 0.75: 1(0,0)
  round 1.5 hole 0.75: 2(2.54,-2.54) 3(0,-5.08)
  silkscreen extent -1.2,-6.09 3.68,1.01, body extent -1.2,-6.09 3.68,1.01, height 8.45
WE-LHMI_4012 [mm] "SMD, 2-Leads, Body 4.06x4.06mm Pitch 2.7mm"
  rect 1.5x2.3 smd: 1(-1.85,0) 2(1.85,0)
  silkscreen extent -2.15,-2.15 2.15,2.15, body extent -2.15,-2.15 2.15,2.15, height 1.2

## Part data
C1 C18: "CAP, CERM, 1 µF, 35 V, +/- 10%, X5R, 0603"
C2 C5 C12: "CAP, CERM, 1000 pF, 50 V, +/- 5%, C0G/NP0, 0402"
C3 C17: "CAP, CERM, 10 µF, 25 V, +/- 10%, X5R, 0805"
C4: "CAP, CERM, 10 µF, 25 V, +/- 10%, X7S, 0805"
C6 C14 C20: "CAP, CERM, 4.7 µF, 16 V, +/- 10%, X5R, 0603"
C7: "CAP, CERM, 0.047 µF, 25 V, +/- 10%, X7R, 0402"
C8: "CAP, CERM, 110 pF, 25 V, +/- 5%, C0G/NP0, 0402"
C9 C10 C13 C19: "CAP, CERM, 10 µF, 10 V, +/- 10%, X7R, 0805"
C11: "CAP, CERM, 0.1 µF, 25 V, +/- 20%, X7R, 0402"
C15: "CAP, CERM, 1 µF, 25 V, +/- 10%, X7R, 0805"
C16: "CAP, CERM, 0.1 µF, 25 V, +/- 10%, X7R, 0402"
D1: "Diode, TVS, Uni, 13 V,  W, SOD-123W"
D2 D7: "Diode, Schottky, 40 V, 0.38 A, SOD-523"
D3 D6: "Diode, Schottky, 20 V, 1 A, 152AD"
D4 D5: "LED, Green, SMD"
FID1 FID2 FID3 FID4 FID5 FID6: "Fiducial mark.  There is nothing to buy or mount."
H1 H2 H3 H4: "Machine Screw, Round, #4-40 x 1/4, Nylon, Philips panhead"
H5 H6 H7 H8: "Standoff, Hex, 0.5\"L #4-40 Nylon"
J1 J2 J4: "Conn Term Block, 2POS, 3.81mm, TH"
J3: "Connector, Receptacle, Micro-USB Type B, R/A, Bottom Mount SMT"
J5: "Terminal Block Receptacle, 3x1, 3.81mm, R/A, TH"
J6: "Header (friction lock), 100mil, 4x1, R/A, TH"
J7: "Header (shrouded), 100mil, 5x2, High-Temperature, Gold, TH"
JP1 JP4 JP8 JP9: "Header, 100mil, 3x1, Tin, TH"
JP2 JP3 JP5 JP6 JP7 JP10 JP11 JP12 JP13 JP14 JP15 JP16 JP17 JP18: "Header, 100mil, 2x1, Tin, TH"
L1: "Inductor, Wirewound, 1 µH, 4 A, 0.041 ohm, SMD"
L2: "Inductor, 1 µH, 3.2 A, 0.028 ohm, SMD"
LBL1: library part THT-14-423-10, "Thermal Transfer Printable Labels, 0.650\" W x 0.200\" H - 10,000 per roll"
Logo1: library part TI_Logo, "Texas Instrument Corporate Signature"
Logo2: library part Pb-Free
Logo3: library part FCC_disclaimer, "FCC_disclaimer"
NT1: "Single point connection between nets."
Q1: "MOSFET, N-CH, 30 V, 22 A, DQK0006C (WSON-6)"
R1: "RES, 0, 5%, 0.1 W, 0603"
R2 R16 R21 R25 R27: "RES, 0, 5%, 0.063 W, 0402"
R3: "RES, 1.00 k, 1%, 0.063 W, 0402"
R4: library part CRCW040210K0FKED, "RES, 10.0 k, 1%, 0.063 W, 0402"
R5 R6 R13 R14 R24 R29: "RES, 10.0 k, 1%, 0.063 W, 0402"
R7 R17: "RES, 2.21 k, 1%, 0.063 W, 0402"
R8: "RES, 221, 1%, 0.063 W, 0402"
R9: "RES, 2.80 k, 1%, 0.063 W, 0402"
R10 R11: "Trimmer, 10k ohm, 0.25W, TH"
R12: "RES, 158, 1%, 0.063 W, 0402"
R15: "RES, 4.7 k, 5%, 0.063 W, 0402"
R18 R30 R31: "RES, 0.01, 1%, 1 W, 2010"
R19 R20: "RES, 200, 1%, 0.063 W, 0402"
R22: "RES, 5.23 k, 1%, 0.063 W, 0402"
R23: "RES, 30.1 k, 1%, 0.063 W, 0402"
R26: "RES, 10, 5%, 0.063 W, 0402"
S1: "Switch, Normally open, 2.3N force, 200k operations, SMD"
S2: "Switch, SPST, 2 Pos, 25mA, 24VDC, SMD"
SH-JP1 SH-JP2 SH-JP3 SH-JP4 SH-JP5 SH-JP6 SH-JP7 SH-JP8 SH-JP9 SH-JP10 SH-JP11 SH-JP12 SH-JP13 SH-JP14 SH-JP15 SH-JP16 SH-JP17 SH-JP18: "Shunt, 100mil, Gold plated, Black"
SW1 SW2 SW3 SW4: library part 131-5031-00, "Compact Probe Tip Circuit Board Test Points, TH, 25 per"
TP1 TP2: "Test Point, Miniature, Red, TH"
TP3 TP4 TP6 TP7 TP10 TP11 TP12 TP13 TP14 TP15 TP16 TP21 TP24 TP25 TP26 TP27 TP28 TP29: "Test Point, Miniature, White, TH"
TP5 TP8: "Test Point, Miniature, Orange, TH"
TP9: "Test Point, Miniature, Yellow, TH"
TP17 TP18 TP19 TP20 TP22 TP23: "Test Point, Compact, SMT"
U1: library part bq25606RGER, "BQ25606RGER, RGE0024H (VQFN-24)"
U1: "BQ25600RTW, RTW0024H (WQFN-24)"
ZZ1: library part AssemblyNoteLabel
ZZ2 ZZ3 ZZ4 ZZ5: library part AssemblyNote

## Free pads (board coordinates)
  rect 220x60 smd: 0(1910,2415)

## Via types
v1: diameter 22, hole 10, Top Layer to Bottom Layer, tented both sides, 573 vias
v2: diameter 19.68, hole 7.87, Top Layer to Bottom Layer, 14 vias

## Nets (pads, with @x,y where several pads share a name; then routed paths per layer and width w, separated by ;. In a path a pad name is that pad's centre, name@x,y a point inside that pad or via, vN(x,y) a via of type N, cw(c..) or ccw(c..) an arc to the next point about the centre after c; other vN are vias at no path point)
/CE: JP2.2 R14.2 R16.2 R21.2 TP16.1 U1.9 | length 3390.6
  Top Layer w9: v1@1675.16,1715 U1.9@1675.16,1855.2
  Signal Layer 2 w10: JP2.2@1450,150 TP16.1@1450,375 ; 1450,285 1450,290 TP16.1@1450,400 1450,640 1600,790 1600,1355 1675,1430 v1(1675,1715)
  Bottom Layer w10: R16.2@475,486.38 475,175 580,70 R21.2@1031.38,70 1031.38,43.62 1045,30 1330,30 JP2.2@1450,150 ; TP16.1@1450,400 1451.38,401.38 R14.2@1540,401.38
/QON_VSET: JP9.2 R15.2 TP15.1 U1.12 | length 2326.7
  Top Layer w9: U1.12@1734.21,1855.2 1734.21,1818.79 1765,1788 1765,1760 1775,1750 1810,1750 1830,1730 v1(1830,1680)
  Top Layer w10: v1(2640,1065) R15.2@2671.38,1065 2671.38,818.62 2865,625 TP15.1@2865,505
  Signal Layer 2 w10: v1(1830,1680) 2445,1065 v1(2640,1065) ; JP9.2@2865,150 TP15.1@2865,505
ACDRV: D7.1 R2.1 TP12.1 U1.2 | length 756.6
  Top Layer w10: TP12.1@905,1905 1385,1905 1405,1885 1460,1885 1514.68,1939.68 R2.1@1514.68,1960 1515.16,1959.53 U1.2@1610.2,1959.53
AGND: C6.2 C16.2 JP1.1 JP2.1 JP3.1 JP5.1 JP9.1 NT1.2 R3.1 R9.1 R10.3 R11.3 R23.1 R24.1 R29.1 S1.2 TP20.1 TP22.1 TP23.1 | length 1360
  Top Layer w10: v1(1310,1935) v1@1310.31,1935.31 ; C6.2@1660,2197.56 1667.44,2205 1670,2205 1665,2210 v1(1665,2225)
  Top Layer w15: v1@1310.31,1935.31 C16.2@1335,1935.31
  Signal Layer 2 w10: JP1.1@1130,1560 1180,1560 1360,1740 ; 1365,1740 1360,1740 ; v1(1665,2225) 1515,2225 1310,2020 v1(1310,1935) 1285,1910 1285,1860 1310,1835 1450,1835 1470,1815 1470,1755 1455,1740 1360,1740
  other v1: 1183,91 1308,91 1808,91 3058,91 3183,91 3308,91 1370.5,216 1495.5,216 1620.5,216 1745.5,216 1870.5,216 1995.5,216 2120.5,216 2370.5,216 2620.5,216 2745.5,216 2995.5,216 1183,341 1308,341 1558,341 1683,341 1808,341 1933,341 2058,341 2183,341 2433,341 2558,341 2683,341 2808,341 2933,341 1245.5,466 1370.5,466 1495.5,466 1620.5,466 1745.5,466 1870.5,466 1995.5,466 2120.5,466 2370.5,466 2620.5,466 2745.5,466 2995.5,466 3120.5,466 3370.5,466 1183,591 1308,591 2058,591 2183,591 2308,591 2433,591 2558,591 2683,591 2808,591 2933,591 3058,591 3308,591 1120.5,716 1370.5,716 1620.5,716 1745.5,716 1870.5,716 1995.5,716 2120.5,716 2370.5,716 2620.5,716 2870.5,716 2995.5,716 3120.5,716 3245.5,716 1645,795 1760,795 808,841 933,841 1058,841 1308,841 1933,841 2058,841 2183,841 2308,841 2433,841 2558,841 2808,841 2933,841 3058,841 3183,841 3308,841 2375,945 870.5,966 995.5,966 1370.5,966 1495.5,966 1745.5,966 1870.5,966 2120.5,966 2620.5,966 2745.5,966 2995.5,966 3120.5,966 3245.5,966 1183,1091 1308,1091 1808,1091 2058,1091 2183,1091 2558,1091 2808,1091 2933,1091 3058,1091 3183,1091 870.5,1216 995.5,1216 1120.5,1216 1370.5,1216 1495.5,1216 1995.5,1216 1370,1340 1058,1341 1558,1341 1808,1341 1940,1410 1120.5,1466 1245.5,1466 1370.5,1466 1745.5,1466 1715,1570 1800,1725
BAT: C12.2 C13.2 C14.2 C20.2 JP4.3 JP8.1 R30.1 SW4.1 TP9.1 TP28.1 U1.13 U1.14 | length 4199.3
  Top Layer w10: U1.14@1759.8,1900.47 2089.53,1900.47 ; R30.1@2734.45,1500 2795,1500 2810,1515 2810,1560 TP28.1@2735,1635
  Signal Layer 2 w10: v1@1860,1870 2430,1870 SW4.1@2440,1860 ; SW4.1@2445,1875 2445,1725 2477.87,1692.13 2781,1692.13 2800,1673.13 2800,1470 2780,1450 2780,1310 2830,1260 3160,1260 TP9.1@3350,1070 ; 2670,1360 2670,1245 2745,1170 3145,1170 3345,970 3345,760 3365,740 3445,740 3460,725 3460,650 JP4.3@3405,595 ; JP8.1@2720,1355 JP8.1@2730,1365 ; JP8.1@2725,1365 2725,1440
  other v1: 2308,1391 2383,1391 2458,1391 2533,1391 2608,1391 2270.5,1466 2345.5,1466 2420.5,1466 2495.5,1466 2570.5,1466 2645.5,1466 2158,1541 2233,1541 2308,1541 2383,1541 2458,1541 2533,1541 2608,1541 2683,1541 2120.5,1616 2195.5,1616 2270.5,1616 2345.5,1616 2008,1691 2083,1691 2158,1691 2233,1691 1970.5,1766 2045.5,1766 2120.5,1766 2195.5,1766 1960,1840 2040,1840 2115,1840 1933,1841 2008,1841 2083,1841 1865,1870
BATSNS_ICHG: J5.3 JP8.2 R8.2 TP6.1 U1.10 | length 2575.7
  Top Layer w9: U1.10@1694.84,1855.2 1694.84,1790.16 v1@1710,1775
  Top Layer w10: v1@1710,1775 1710,1755 R8.2@1715,1750
  Signal Layer 2 w8: v1@1710,1775 1785,1775 1820,1810 1820,1875 1840,1895 2360,1895 2405,1940 2475,1940 2695,1720 2825,1720 ; JP8.2@2825,1365 2825,1720 ; TP6.1@3355,1785 3355,1581.38 J5.3@3350.75,1577.13 3207.87,1720 2825,1720
  other v1: 1710,1776
BTST: R25.2 U1.21 | length 47.6
  Top Layer w10: U1.21@1694.84,2004.8 1694.84,2045.16 R25.2@1700,2050.31
D+_PSEL: JP1.2 JP13.2 TP14.1 U1.3 | length 1249.8
  Top Layer w9: JP1.2@1130,1660 1180,1660 1385,1865 1480,1865 1554.84,1939.84 U1.3@1610.2,1939.84
  Signal Layer 2 w10: JP13.2@495,1665 500,1660 770,1660 790,1640 TP14.1@910,1640 980,1640 1000,1660 JP1.2@1130,1660
D-_/PG: JP14.1 JP15.1 TP13.1 U1.4 | length 1239.2
  Top Layer w9: JP15.1@1415,1790 1455,1790 1585.16,1920.16 U1.4@1610.2,1920.16
  Signal Layer 2 w10: JP14.1@490,1770 500,1760 705,1760 TP13.1@700,1765 ; TP13.1@705,1770 715,1760 990,1760 1035,1715 1255,1715 1330,1790 JP15.1@1415,1790
INT_ILIM: R12.2 R13.2 TP7.1 U1.8 | length 814.4
  Top Layer w9: R12.2@1629.69,1744.69 1655.47,1770.47 U1.8@1655.47,1855.2
  Top Layer w10: TP7.1@1590,1460 1595,1465 1595,1725 1614.69,1744.69 R12.2@1629.69,1744.69
  Bottom Layer w10: R13.2@1525,1103.62 1525,1395 TP7.1@1590,1460
NetC7_1: C7.1 D3.2 D6.1 L1.1 L2.1 R26.2 SW1.1 U1.19 U1.20 | length 1152.3
  Top Layer w10: C7.1@1705,2179.68 1725.32,2179.68 1740,2165 1740,2142.17 1757.17,2125 ; U1.20@1714.53,2004.8 1714.53,2019.53 1730,2035 1730,2055 1730,2087.83
  Top Layer w25: L2.1@1827,2137 L1.1@1827,2285.46
  Signal Layer 2 w10: v1@1730,2055 1960,2285 1960,2355 2025,2420 SW1.1@2025,2605
  Bottom Layer w10: D3.2@1726.81,2085 D3.2@1730,2081.81 ; v1@1730,2055 D3.2@1730,2081.81 ; D3.2@1731.81,2080 D3.2@1731.81,2083.62 ; D3.2@1731.81,2091.5 D3.2@1731.81,2083.62 ; R26.2@1765.31,2140 1765,2140 1735,2110 1735,2093.19 1738.19,2090 ; D6.1@1773.74,2090 1738.19,2090 ; D3.2@1730,2081.81 D3.2@1731.81,2083.62 ; D3.2@1731.81,2083.62 1738.19,2090
  other v1: 1730,2050
NetC7_2: C7.2 D2.1 R25.1 | length 78.7
  Top Layer w10: R25.1@1700,2089.68 v1(1700,2115) C7.2@1700,2140.31
  Bottom Layer w10: v1@1701.65,2116.65 v1(1700,2115) 1700,2138.35 D2.1@1701.65,2140
NetC8_1: C8.1 R26.1 | length 45
  Bottom Layer w10: R26.1@1800.32,2140 C8.1@1845.32,2140
NetC15_1: C15.1 D1.1 J1.2 R31.1 TP24.1 | length 270.8
  Top Layer w10: R31.1@689.45,2170 750,2170 770,2190 770,2282.67 747.67,2305 TP24.1@690,2305
  other v1: 133,2141 208,2141 283,2141 358,2141 433,2141 508,2141 583,2141 245.5,2216 320.5,2216 395.5,2216 620.5,2216
NetC17_2: C17.2 JP17.2 | length 129.1
  Top Layer w10: C17.2@1480,2555 C17.2@1490,2565
  Top Layer w30: C17.2@1490,2565 JP17.2@1490,2680
NetC18_2: C18.2 JP16.2 | length 91.5
  Top Layer w10: JP16.2@1355,2300 JP16.2@1358.5,2296.5
  Top Layer w30: C18.2@1358.5,2210 JP16.2@1358.5,2296.5
NetC19_2: C19.2 JP11.2 | length 110
  Top Layer w30: C19.2@2565,2340 JP11.2@2675,2340
NetC20_1: C20.1 JP18.1 | length 113.9
  Top Layer w10: JP18.1@2498.5,1293.5 JP18.1@2520,1315
  Top Layer w20: C20.1@2415,1293.5 JP18.1@2498.5,1293.5
NetD4_1: D4.1 R17.1 S2.4 | length 294.9
  Top Layer w10: D4.1@1670,714.53 1670,755 1710,795 R17.1@1710,877.32 ; R17.1@1710,881.38 1823.62,881.38 S2.4@1825,880
NetD4_2: D4.2 JP10.2 S2.1 | length 471.2
  Top Layer w10: JP10.2@1440,745 1535,745 1624.53,655.47 D4.2@1670,655.47 1670,625 1715,580 S2.1@1825,580
NetD5_1: D5.1 R7.1 S2.3 | length 321.1
  Top Layer w10: S2.3@1875,880 1998.62,880 2005,886.38 R7.1@2005,881.38 2005,790 2045,750 D5.1@2045,714.53
NetD5_2: D5.2 JP12.2 S2.2 | length 981.5
  Top Layer w10: JP12.2@1250,745 1310,685 1545,685 1705,525 1860,525 1875,540 S2.2@1875,580 2000,580 2045,625 D5.2@2045,655.47
NetD7_2: D7.2 Q1.3 R2.2 | length 98
  Top Layer w10: D7.2@1438.35,1915 1435.59,1917.76 Q1.3@1435.59,1966.61 1437.2,1965 1475,1965 1475.31,1964.69 R2.2@1475.31,1960
NetJ3_2: J3.2 JP14.2 | length 252.2
  Top Layer w10: J3.2@162.36,1722.72 312.72,1722.72 355,1765 390,1765 JP14.2@395,1760
NetJ3_3: J3.3 JP13.1 | length 250.1
  Top Layer w10: J3.3@162.36,1697.13 312.87,1697.13 350,1660 390,1660 JP13.1@395,1665
NetJ4_1: J4.1 R18.2 TP26.1 | length 235.8
  Top Layer w10: TP26.1@3020,2420 2945,2345 2945,2295 2955,2285 R18.2@3020.55,2285
  other v1: 3058,2141 3133,2141 3208,2141 3283,2141 3358,2141 3095.5,2216 3170.5,2216 3245.5,2216 3320.5,2216 3133,2291 3208,2291 3283,2291
NetJ5_2: J5.2 JP8.3 R30.2 TP29.1 | length 742.2
  Top Layer w10: TP29.1@2915,1635 2840,1560 2840,1515 2855,1500 R30.2@2915.55,1500
  Signal Layer 2 w10: JP8.3@2925,1365 2955,1335 3315,1335 3350.75,1370.75 J5.2@3350.75,1427.13
  other v1: 2983,1391 3058,1391 3133,1391 3208,1391 3283,1391 3020.5,1466 3095.5,1466 3170.5,1466 3245.5,1466 2980,1545 3060,1545 3135,1545 3210,1545 3285,1545
NetJ6_4: J6.4 R16.1 | length 465.2
  Bottom Layer w10: J6.4@224.41,895 475,644.41 R16.1@475,533.62
NetJ7_2: J7.2 R21.1 | length 80.6
  Bottom Layer w10: R21.1@1078.62,70 1078.62,148.62 J7.2@1080,150
NetJ7_9: J7.9 R19.2 | length 284
  Bottom Layer w10: R19.2@565,486.38 565,365 J7.9@680,250
NetJ7_10: J7.10 R20.1 | length 403.8
  Bottom Layer w10: R20.1@650,500 730,420 730,200 J7.10@680,150
NetJP1_3: JP1.3 R6.1 | length 178.3
  Top Layer w10: JP1.3@1130,1760 1130,1805 1195,1870 R6.1@1236.38,1870
NetJP6_1: JP6.1 R22.2 | length 213.8
  Bottom Layer w10: R22.2@2438.62,70 2560,70 2590,100 JP6.1@2590,150
NetJP7_2: JP7.2 R24.2 | length 176.4
  Top Layer w10: JP7.2@2340,150 R24.2@2340,326.38
NetJP9_3: JP9.3 R29.2 | length 135.9
  Bottom Layer w10: JP9.3@2765,150 2765,105 2800,70 R29.2@2841.38,70
NetJP12_1: JP12.1 JP15.2 R27.2 | length 1112.6
  Top Layer w9: R27.2@1415,1555.31 JP15.2@1415,1690 ; JP15.2@1415,1690.31 JP15.2@1415,1690 ; JP15.2@1415.31,1690.31 JP15.2@1415,1690
  Signal Layer 2 w10: JP12.1@1250,845 1250,1285 1485,1520 1485,1630 1425,1690 JP15.2@1415,1690
NetR3_2: R3.2 R11.1 R11.2 R12.1 | length 759.7
  Top Layer w10: R3.2@1585,1208.62 1643.62,1208.62 1680,1245 R11.1@1680,1285 1680,1455 1635,1500 R12.1@1635,1705.32
  Signal Layer 2 w10: R11.1@1680,1285 1730,1285 1780,1235 R11.2@1780,1185
NetR8_1: R8.1 R9.2 R10.1 R10.2 | length 929.8
  Top Layer w10: R8.1@1715,1705.32 1710,1700.32 1710,1620 1905,1425 R10.2@1905,1185 ; R10.1@2005,1085 2005,1135 2031.38,1161.38 R9.2@2100,1161.38
  Signal Layer 2 w10: R10.2@1905,1185 1905,1135 1955,1085 R10.1@2005,1085
NetR15_1: R15.1 S1.1 | length 185.4
  Top Layer w10: R15.1@2718.62,1065 2760,1065 2817.95,1007.05 S1.1@2817.95,945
